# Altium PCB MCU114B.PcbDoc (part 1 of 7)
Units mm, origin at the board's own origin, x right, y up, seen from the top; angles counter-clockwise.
Board outline 105.51 x 58.76 mm, 8 copper layers (Top Layer, GND 2, Signal Layer 3, Power 4, Power 5, Signal Layer 6, GND 7, Bottom), stack 1.554 mm thick; 444 components, 418 nets, 1811 pads, 981 vias.
Unrouted connection lines stored in the file: 3.
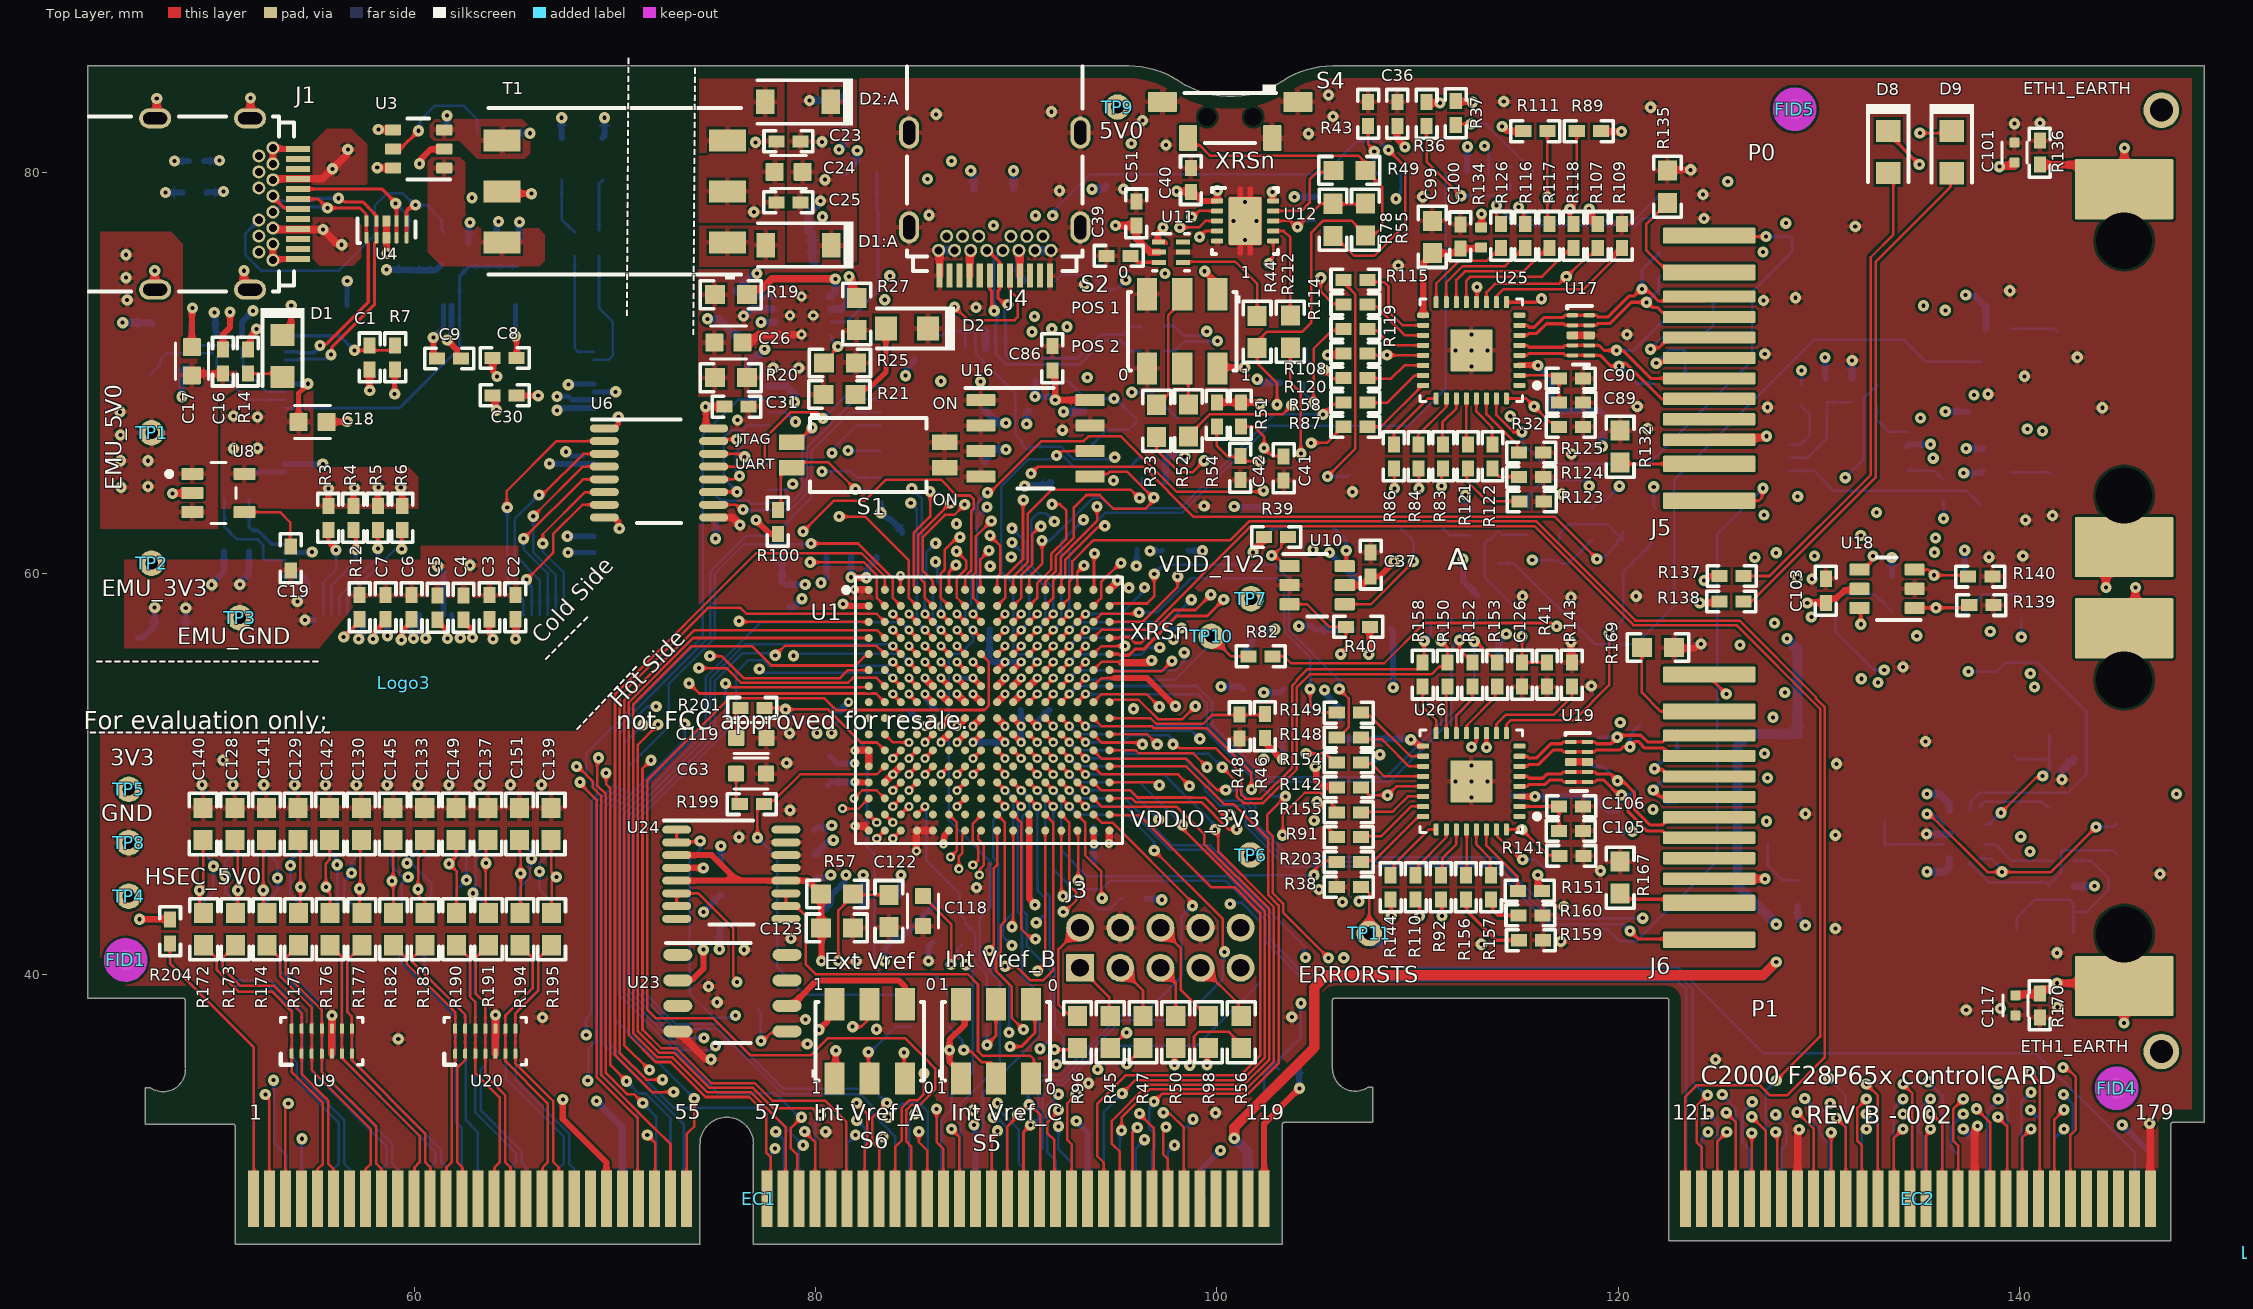
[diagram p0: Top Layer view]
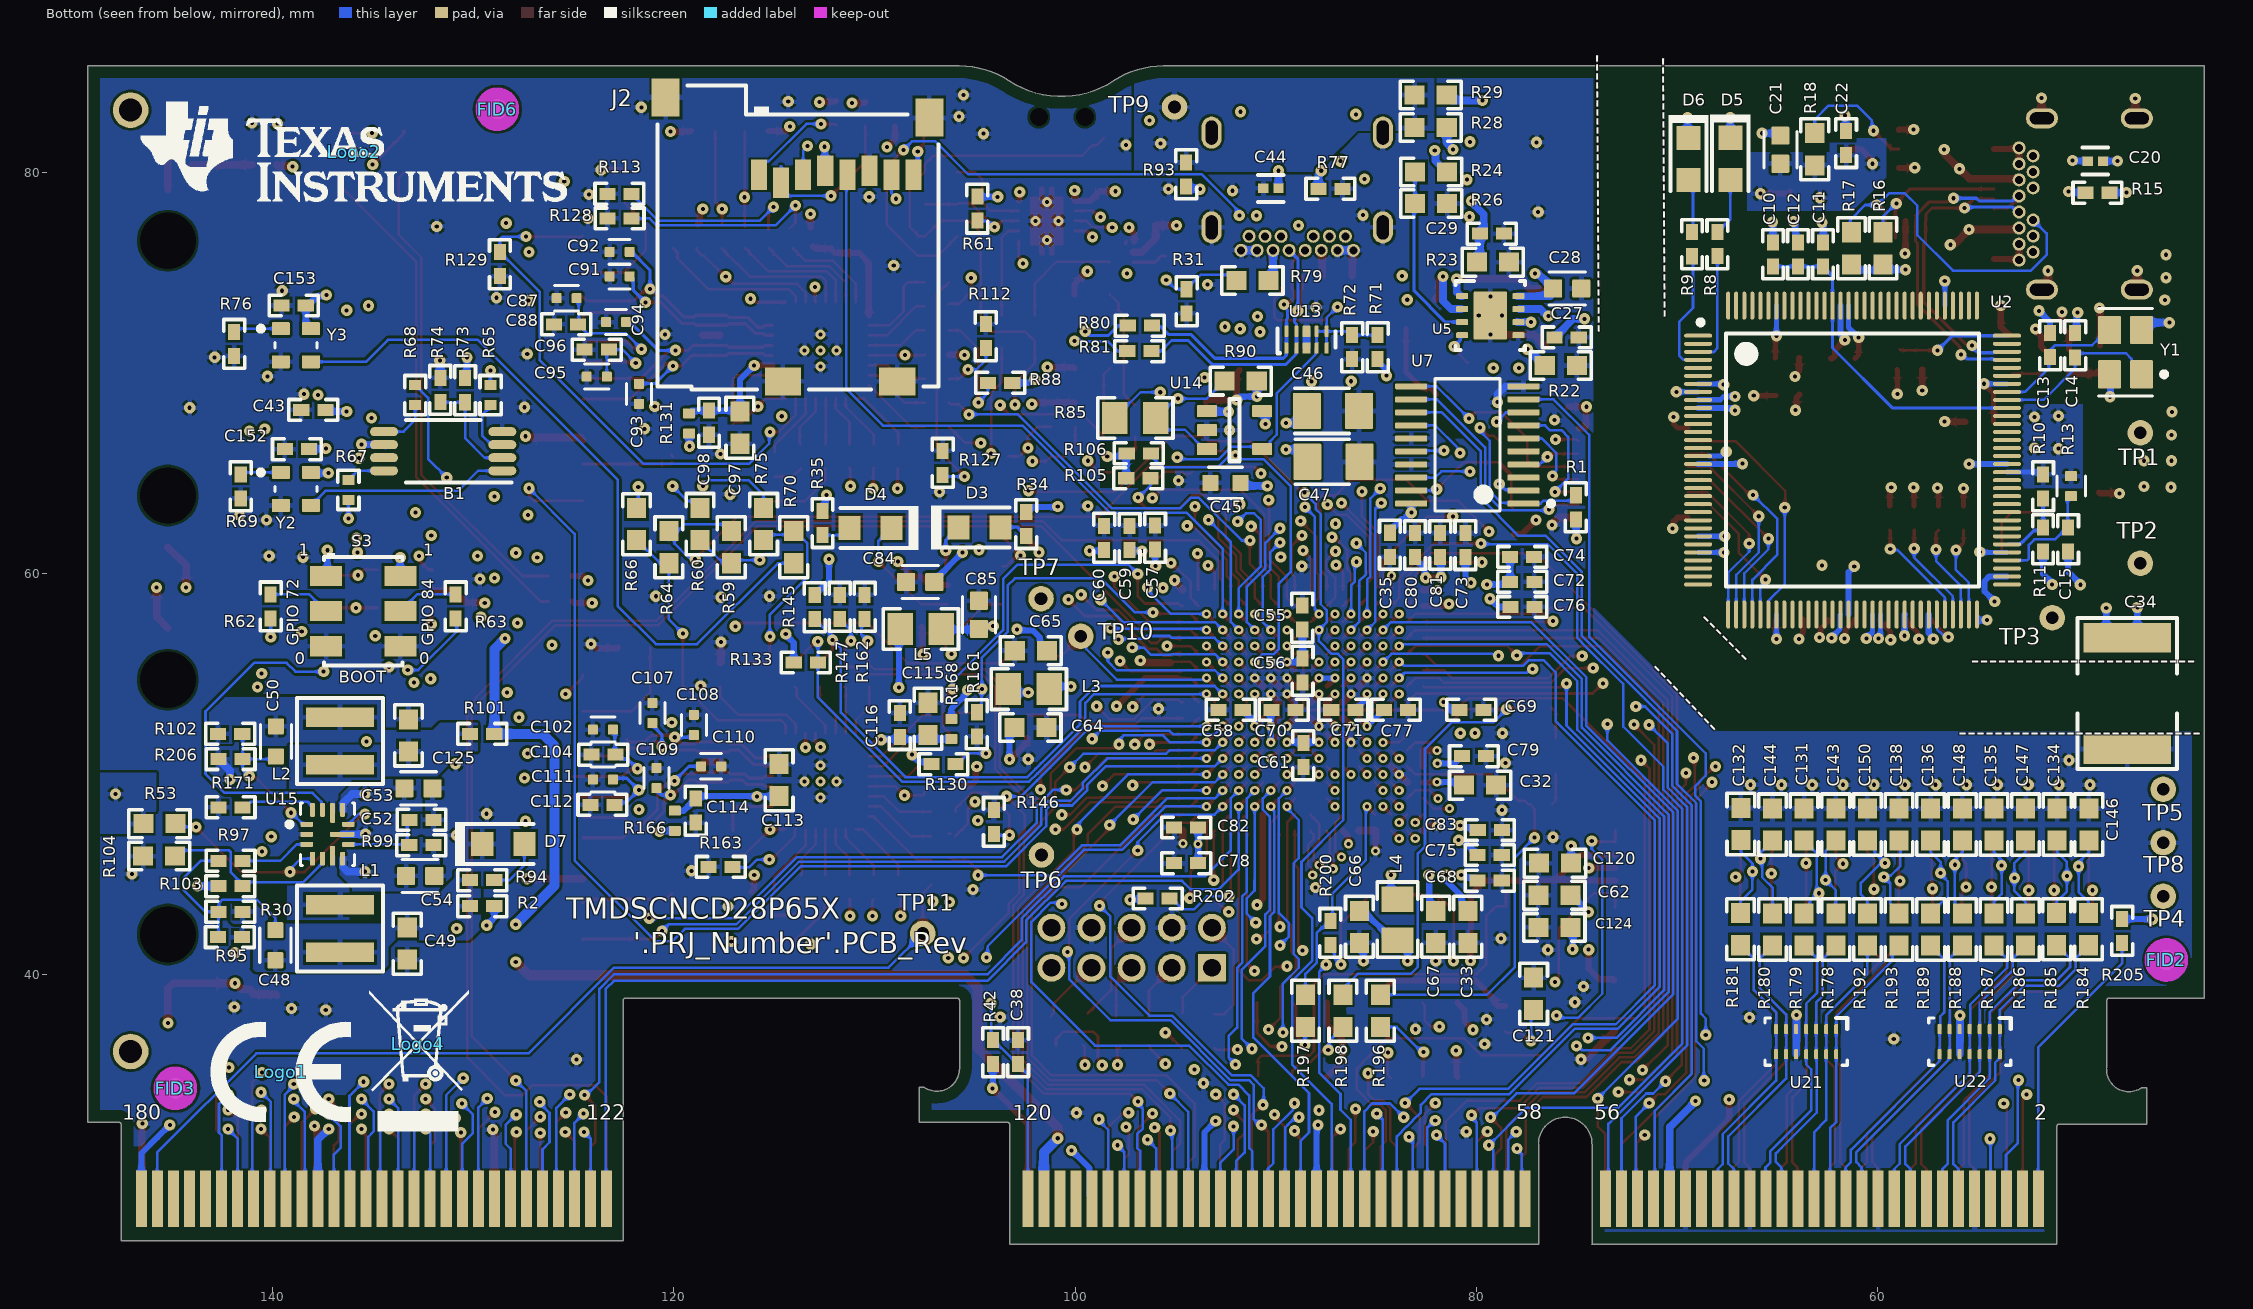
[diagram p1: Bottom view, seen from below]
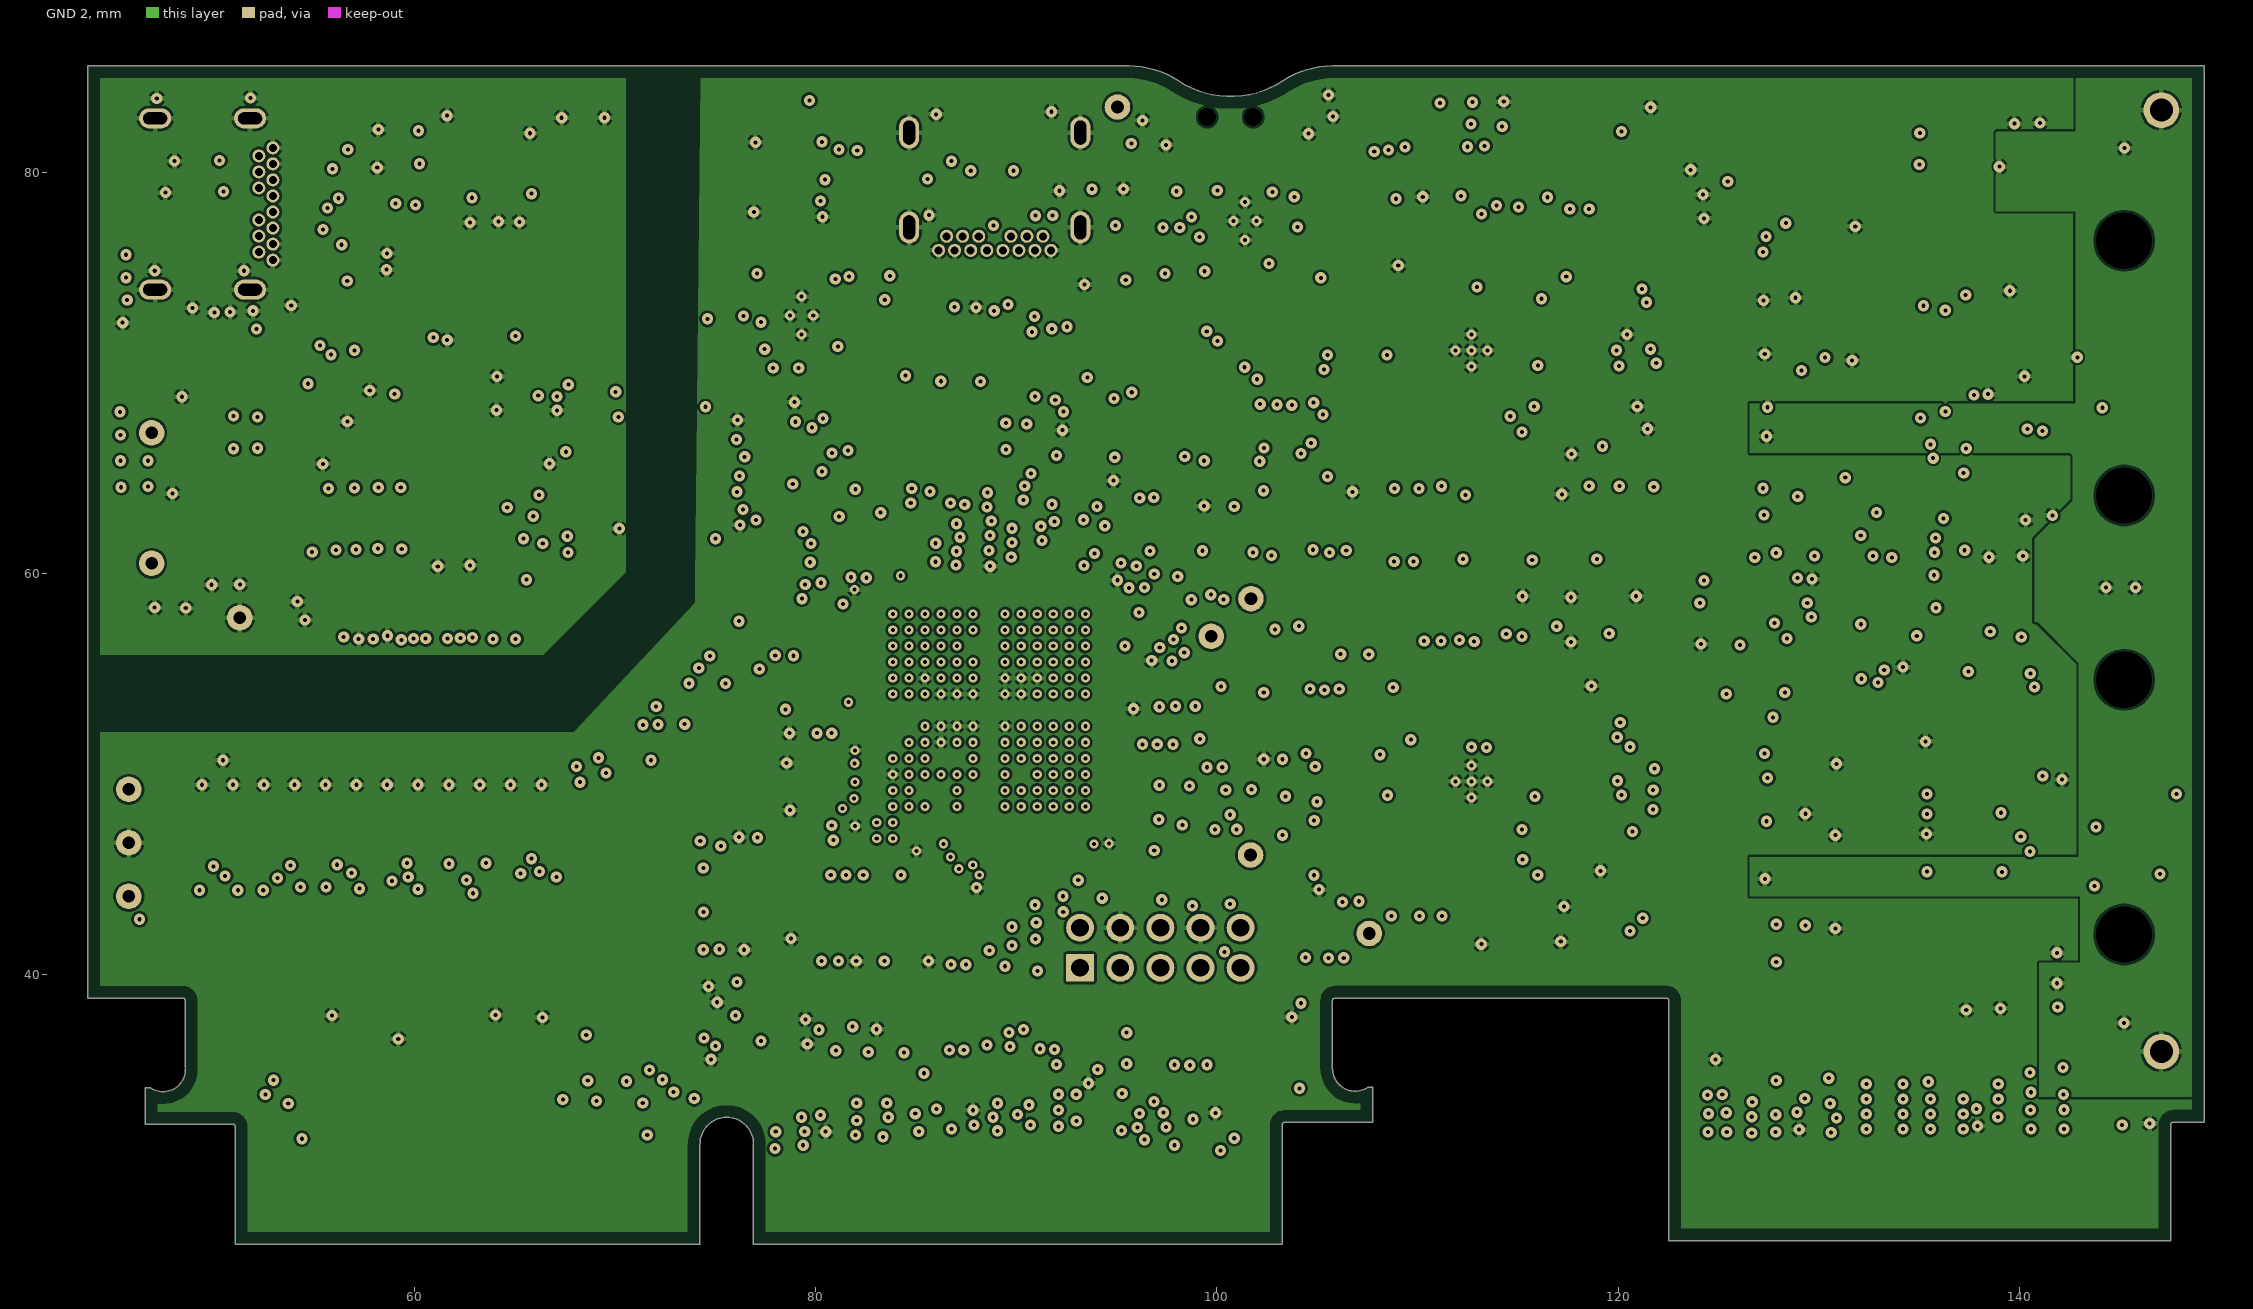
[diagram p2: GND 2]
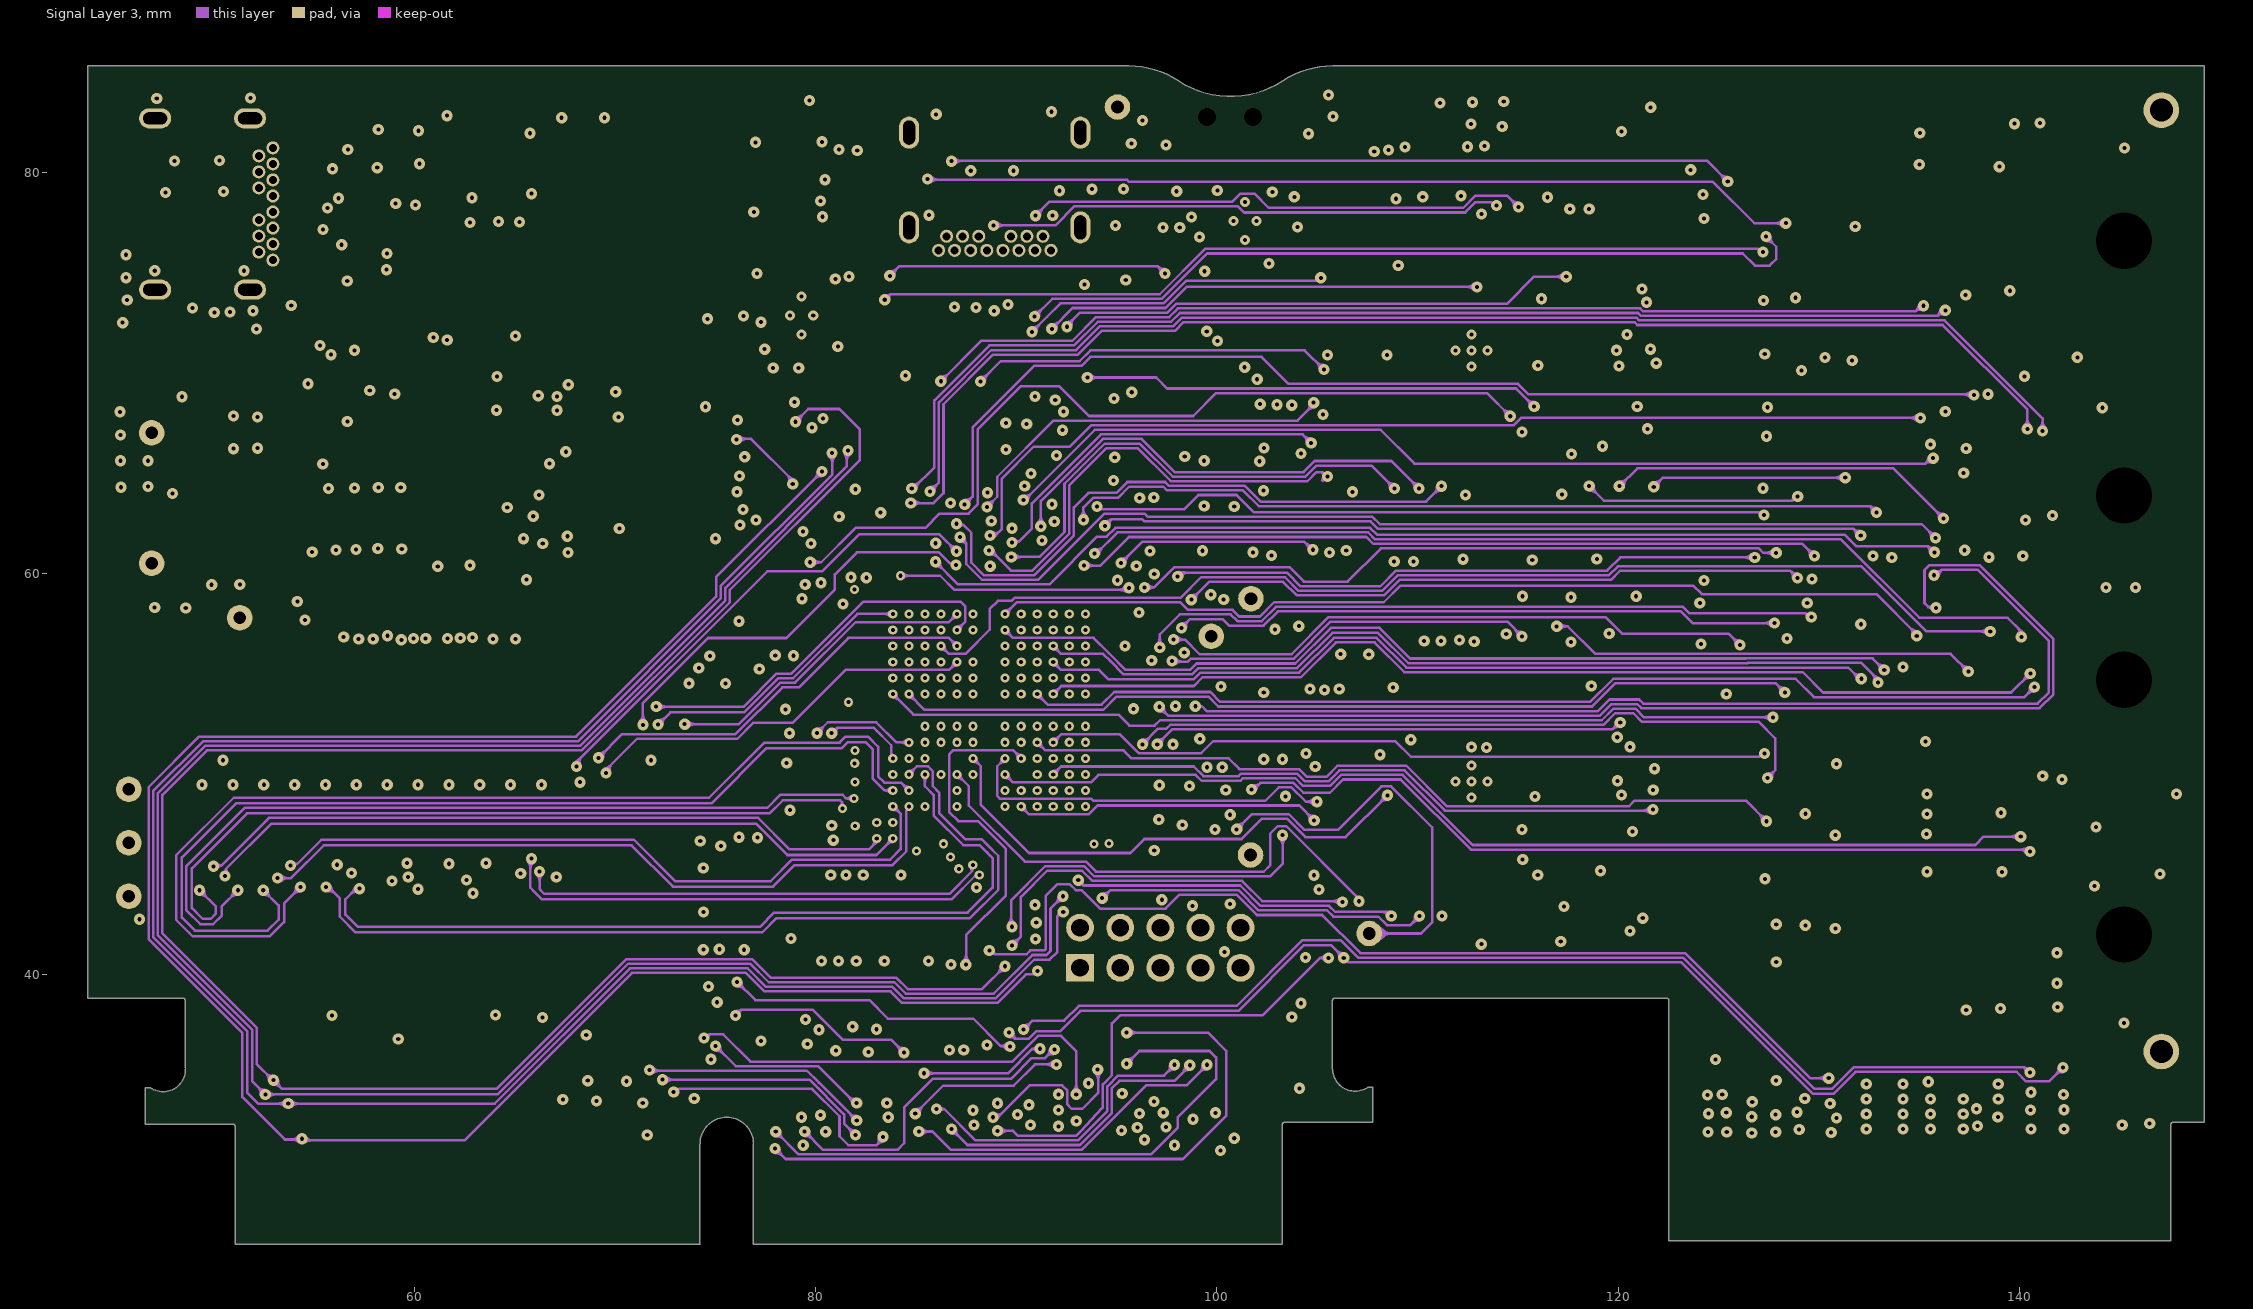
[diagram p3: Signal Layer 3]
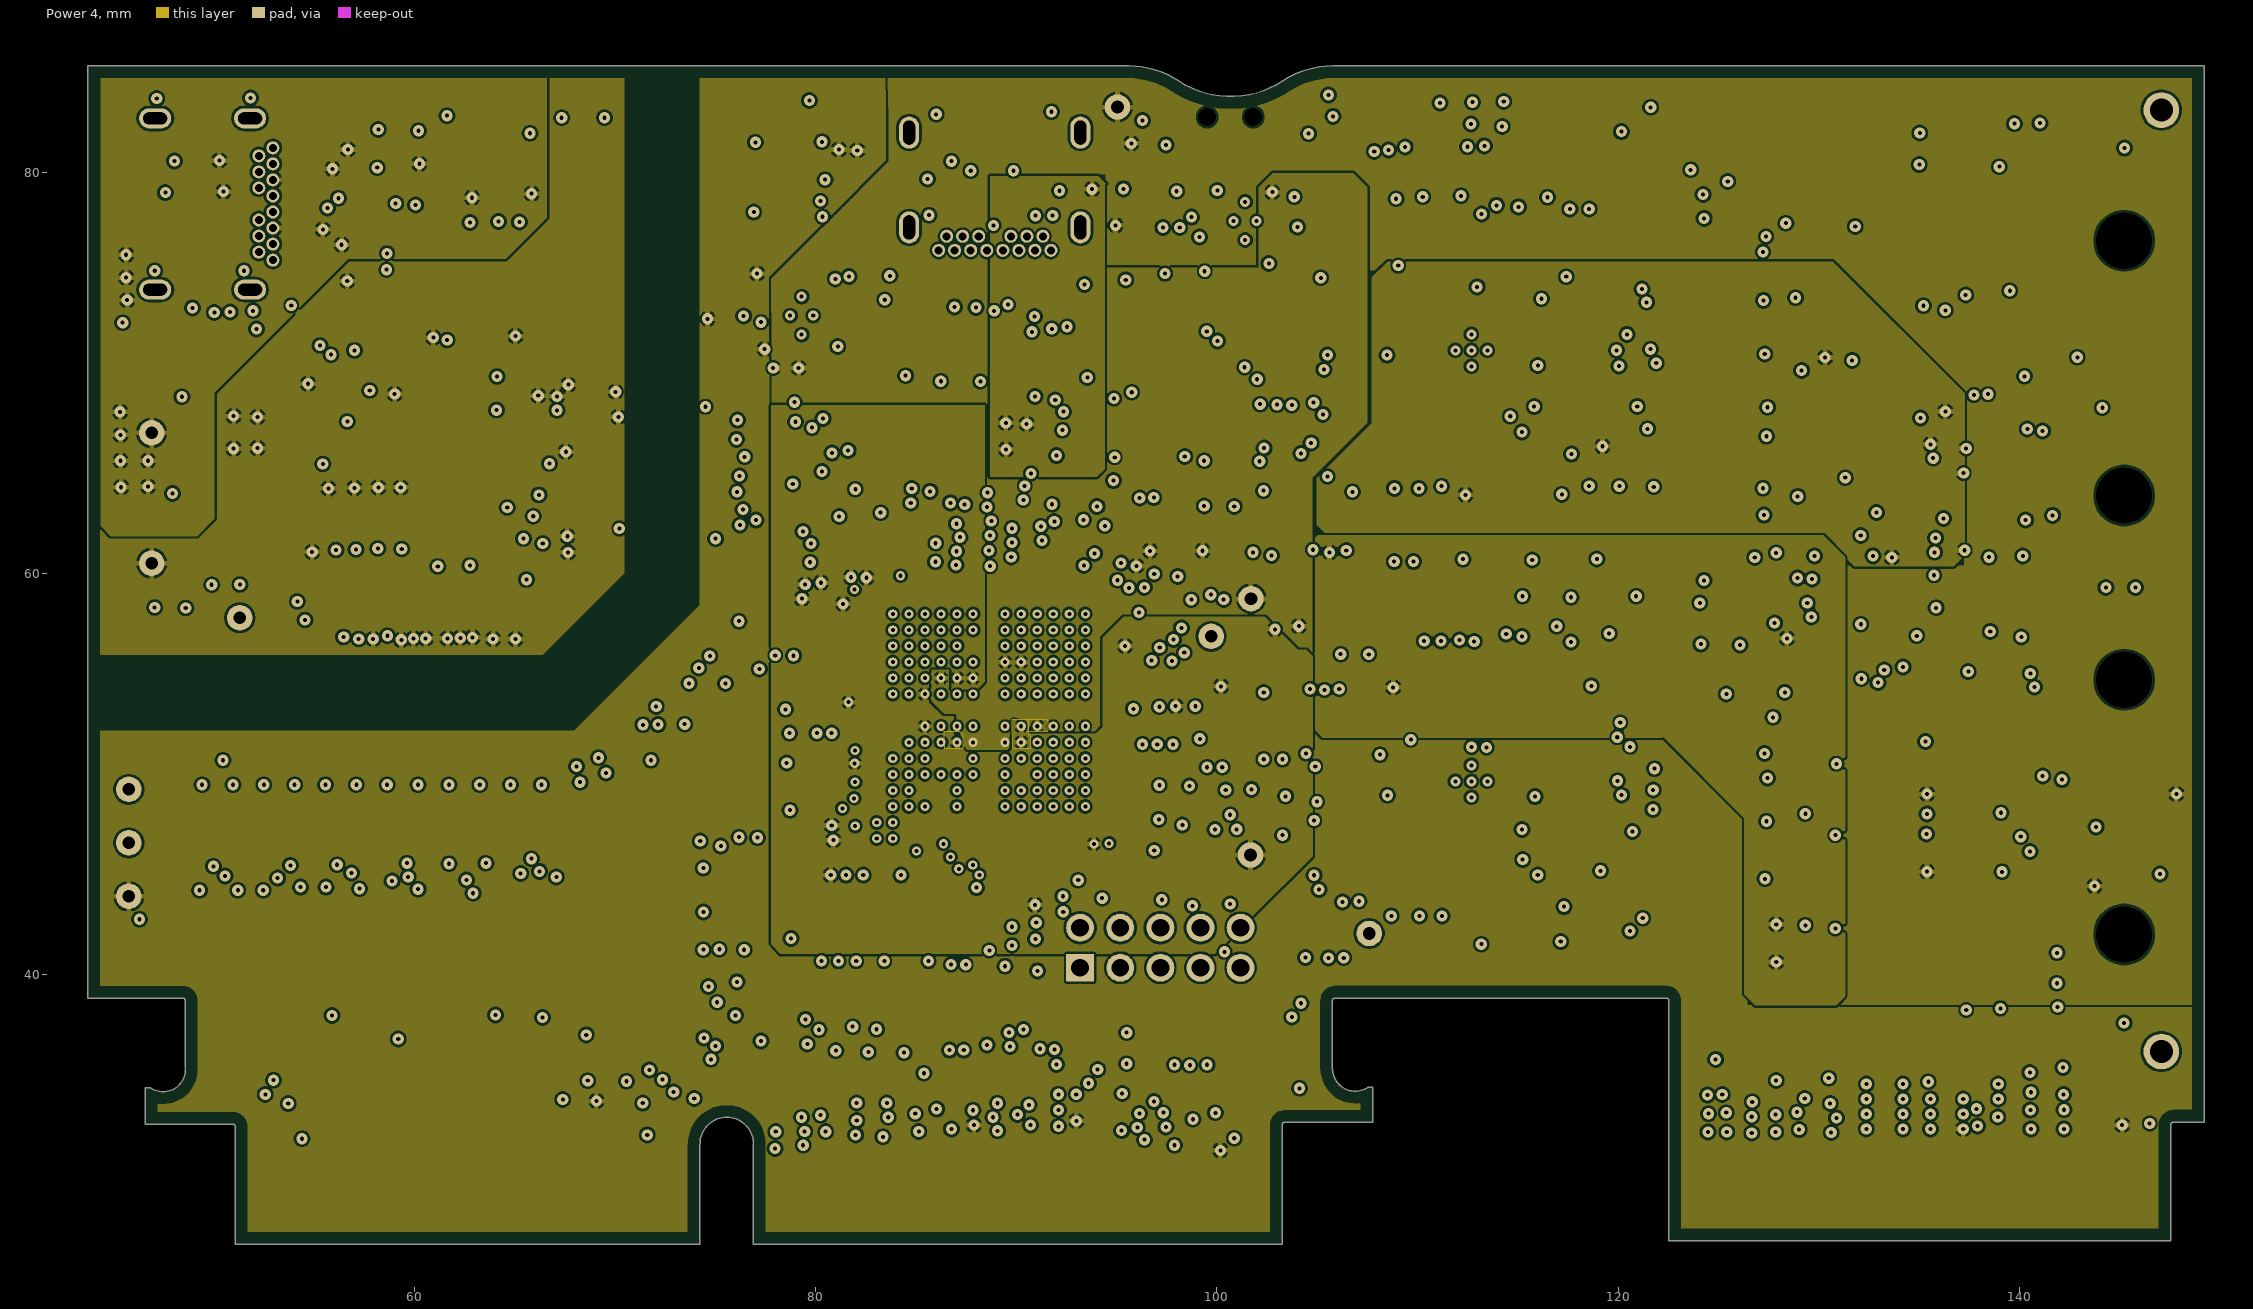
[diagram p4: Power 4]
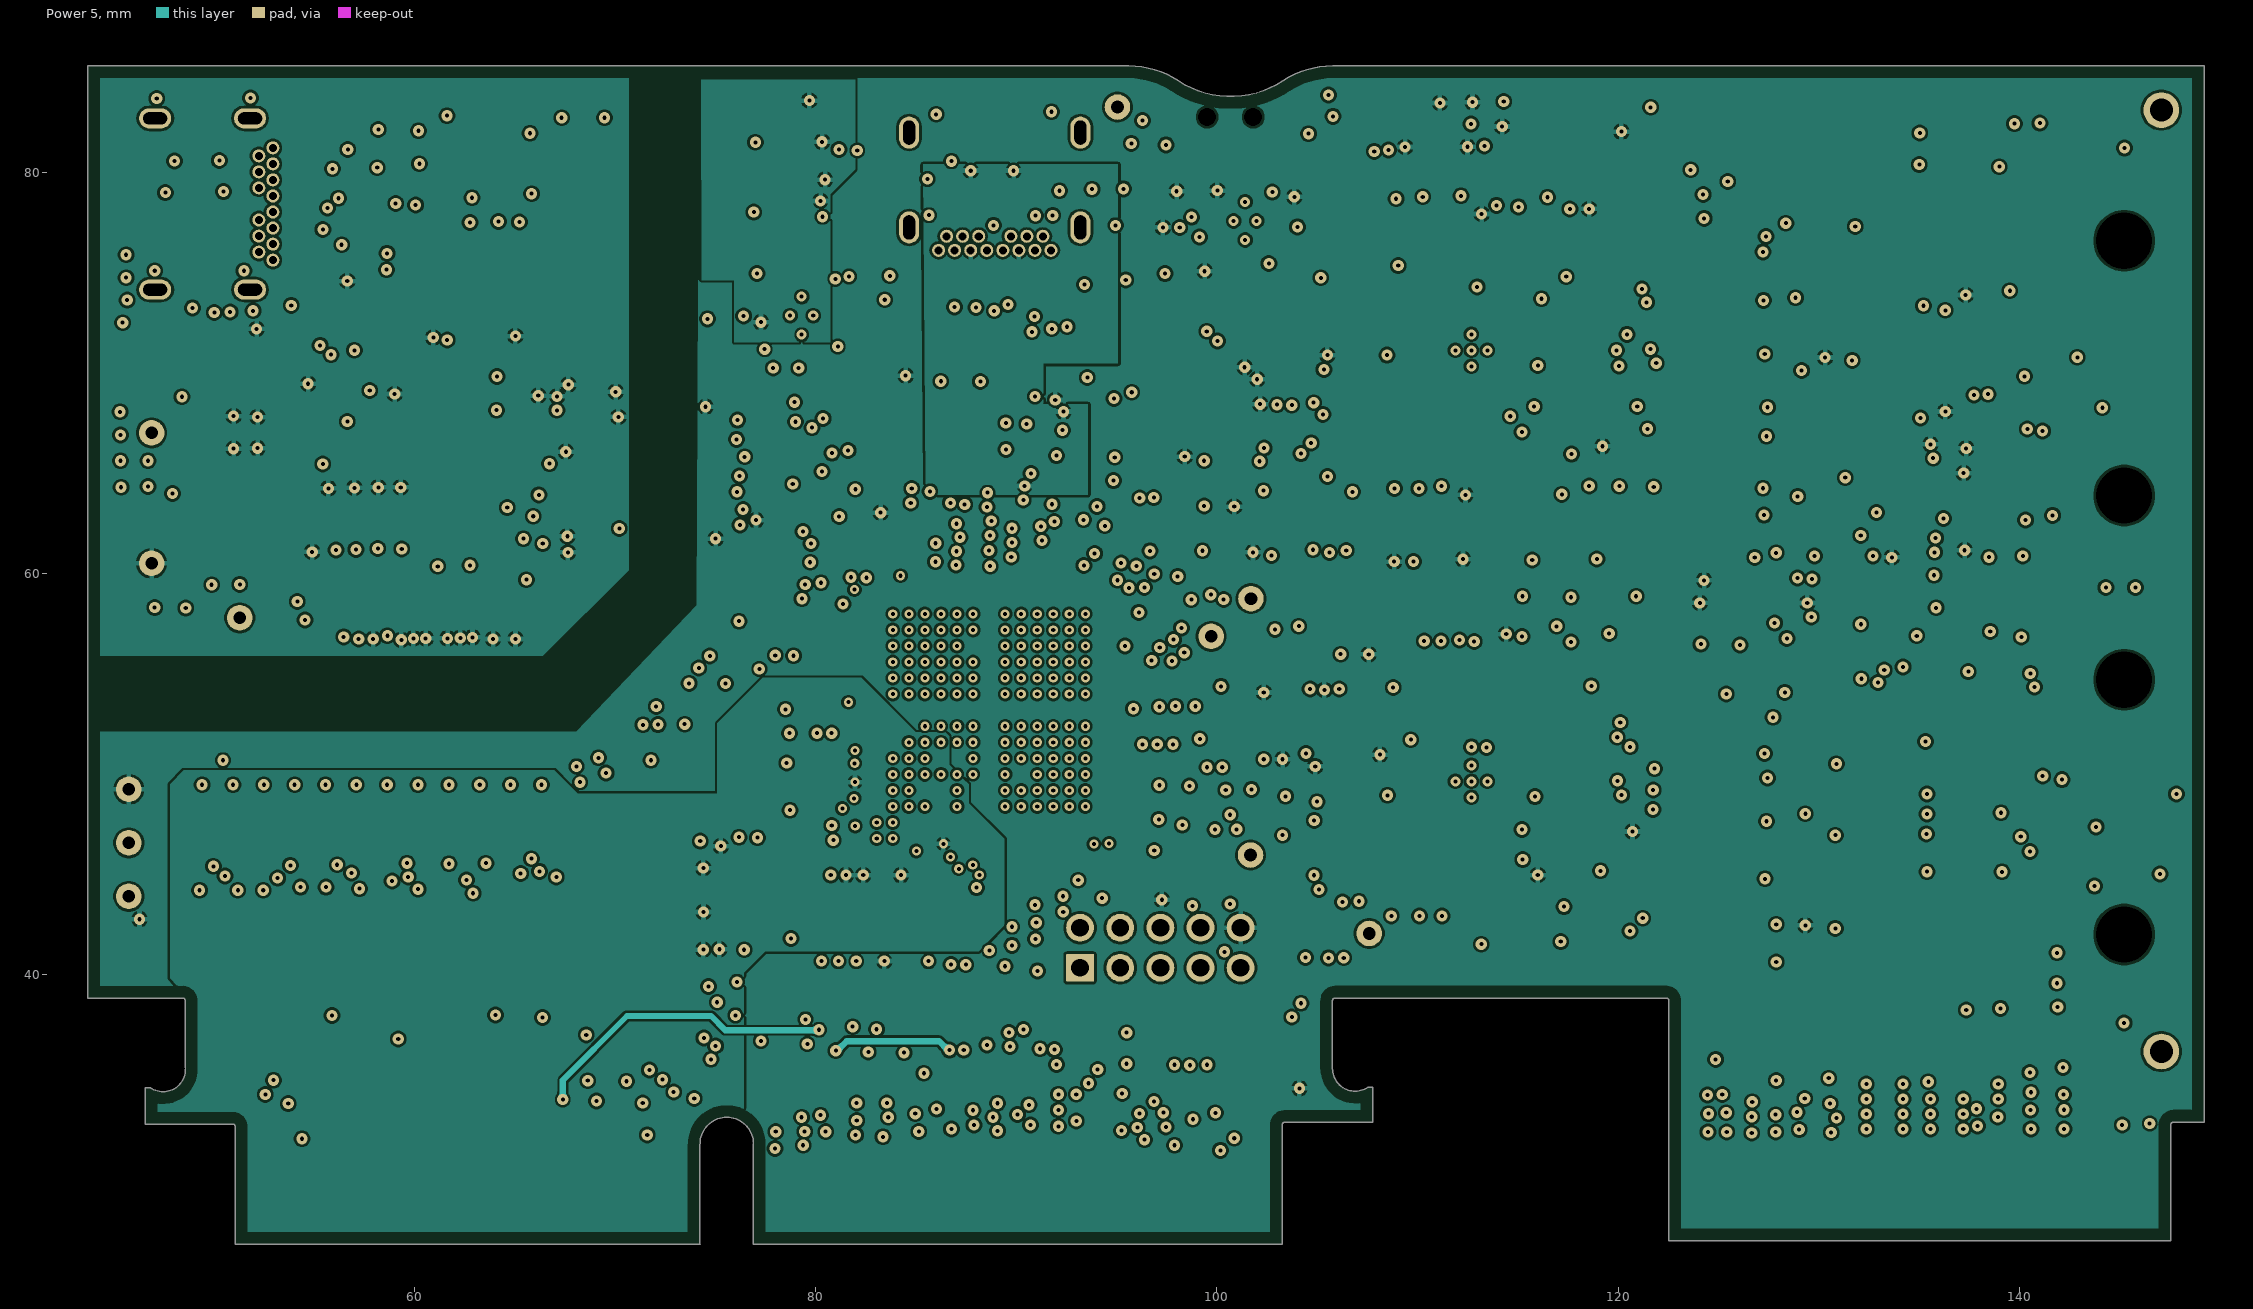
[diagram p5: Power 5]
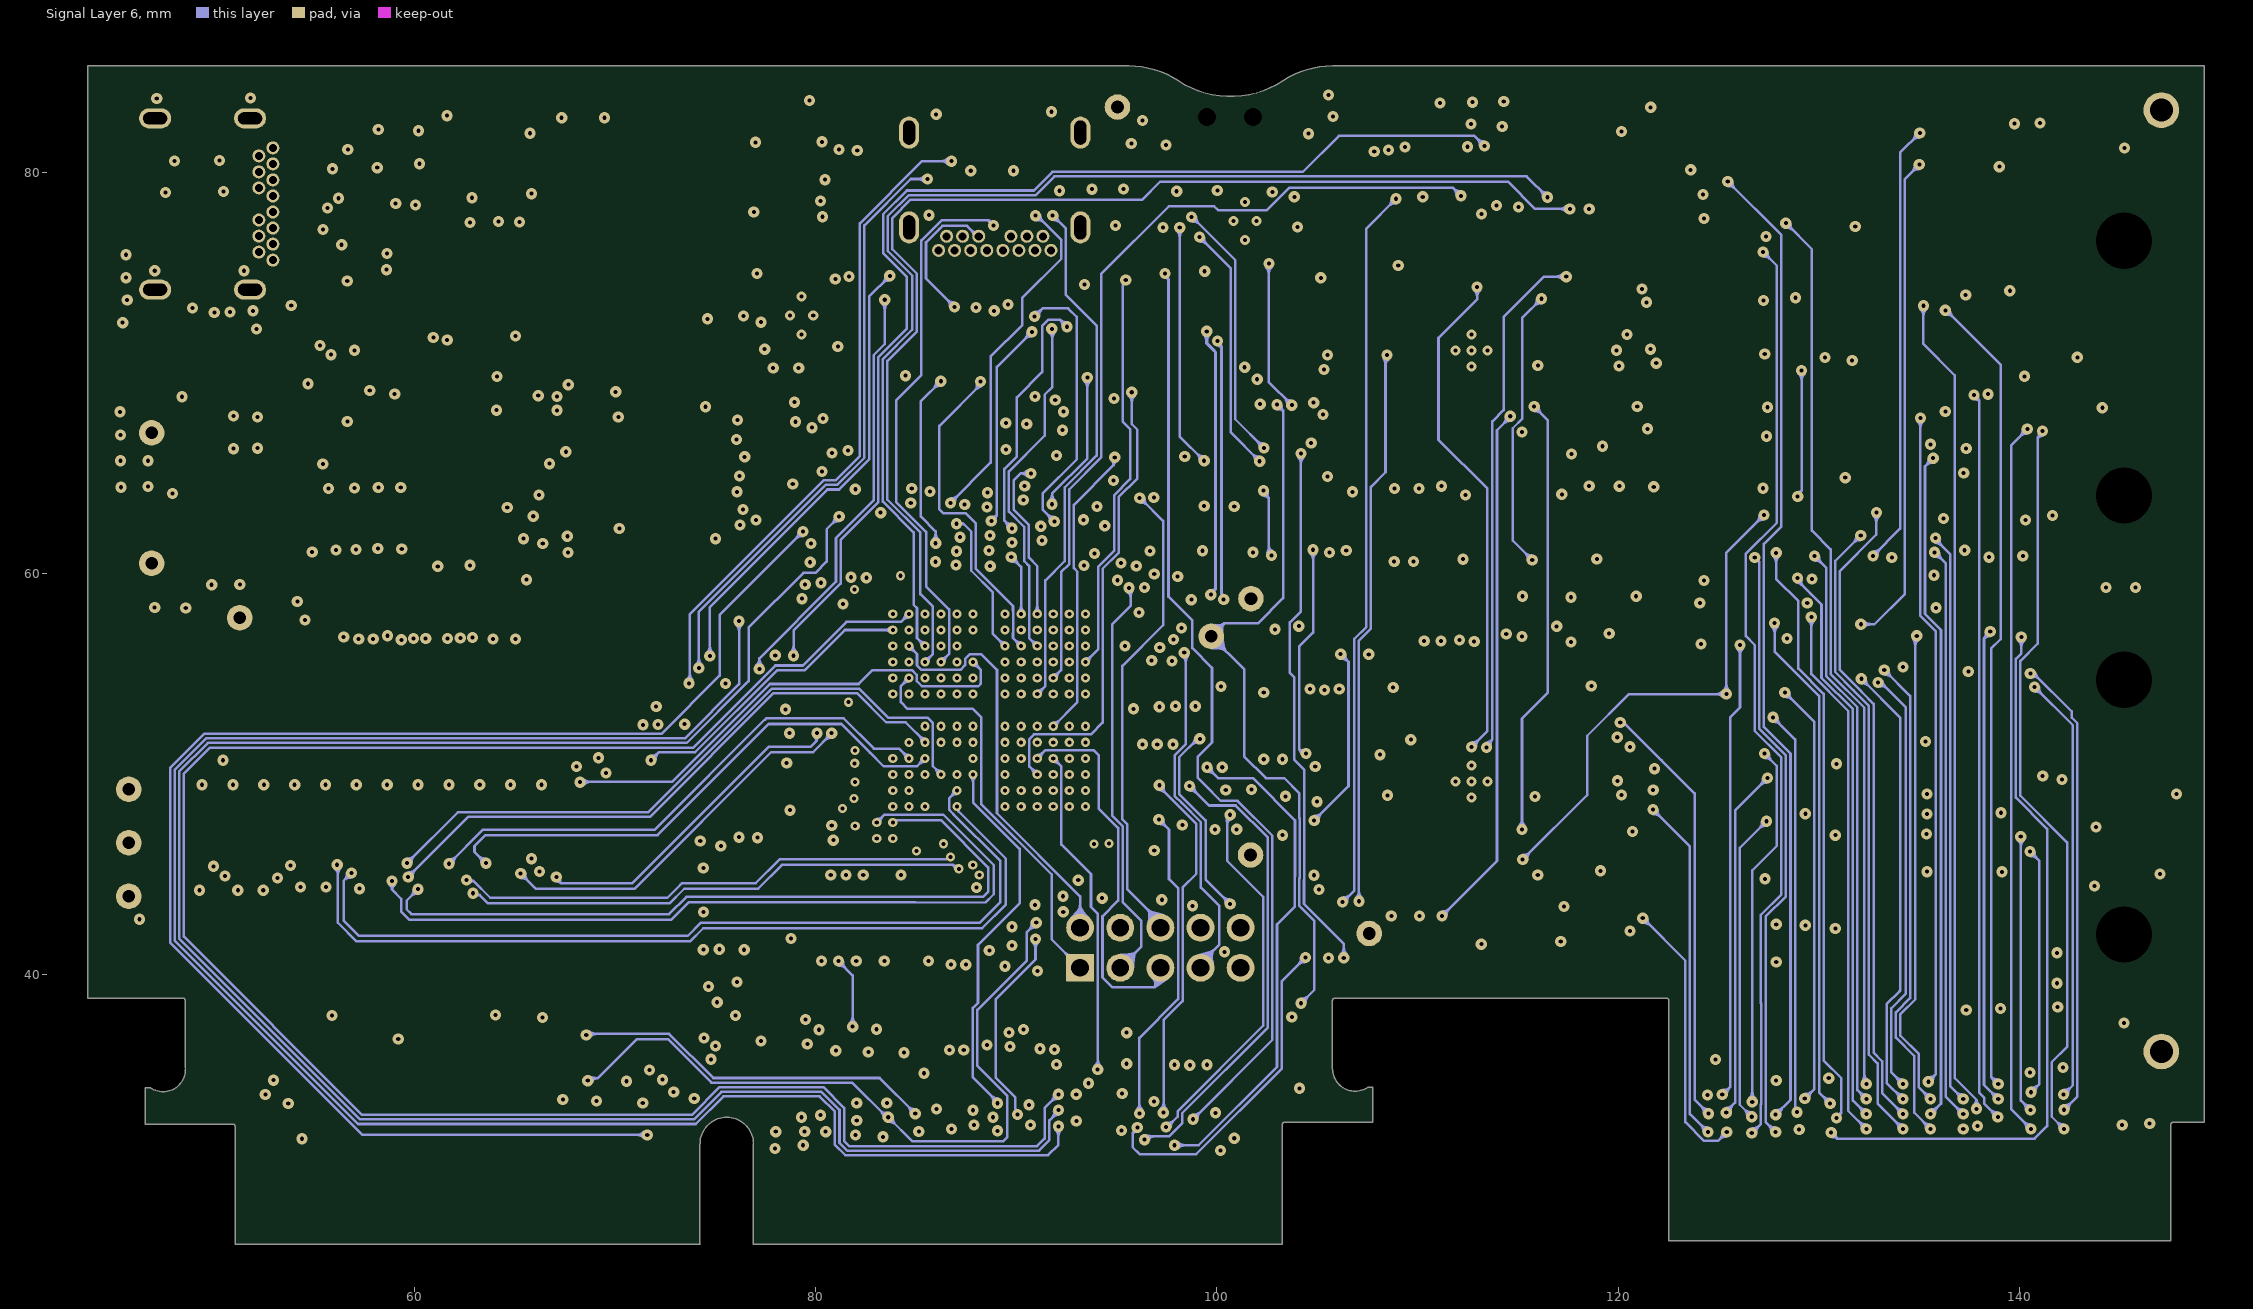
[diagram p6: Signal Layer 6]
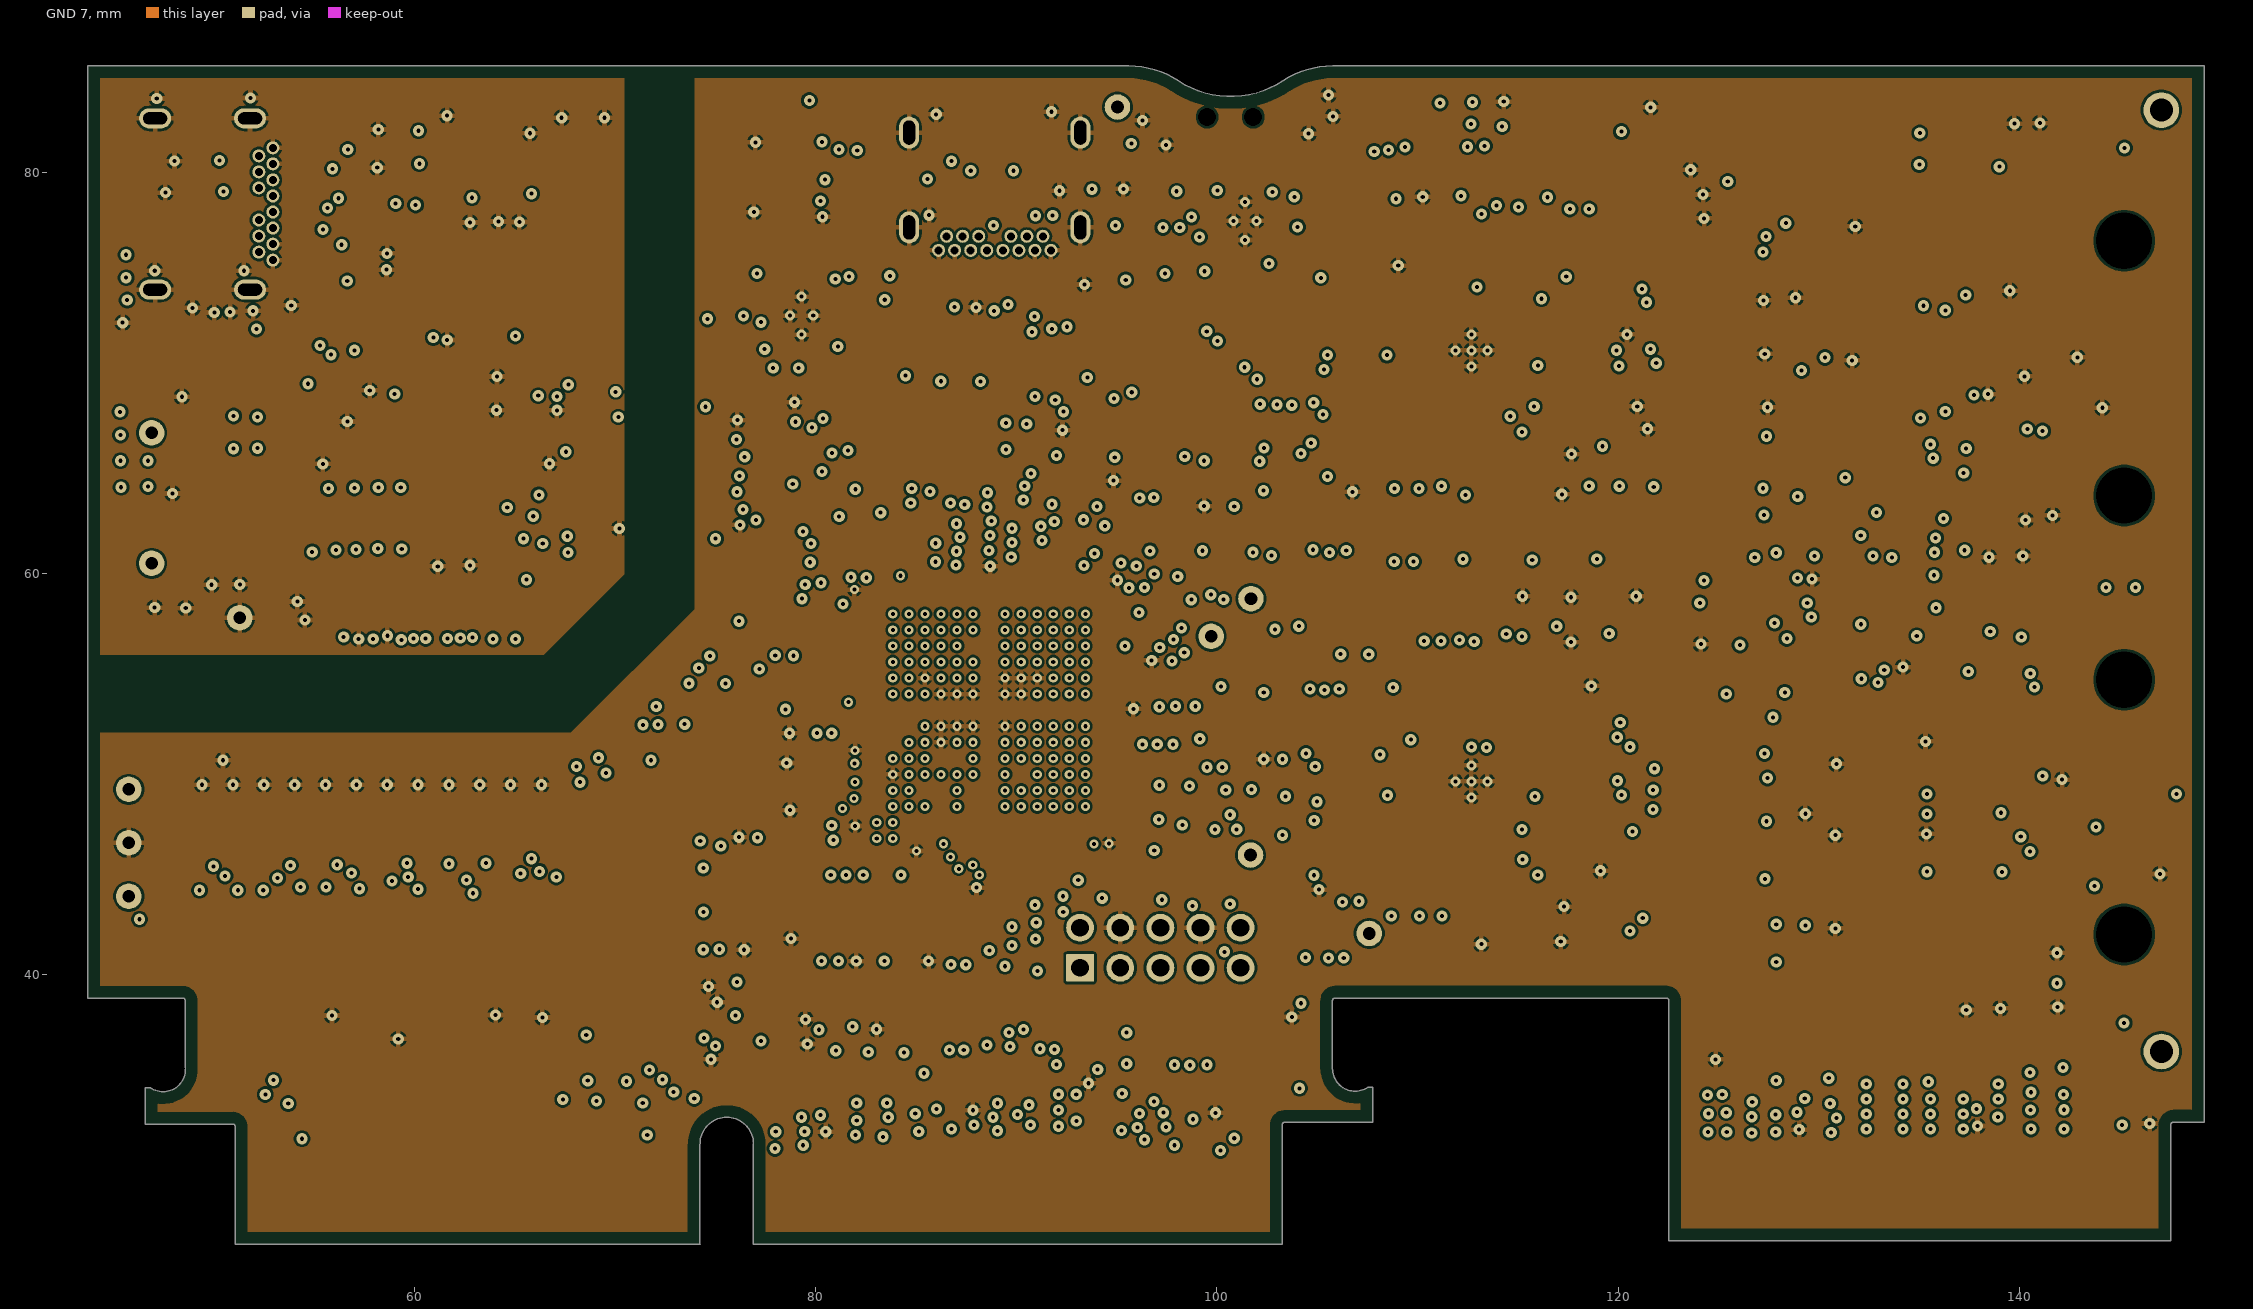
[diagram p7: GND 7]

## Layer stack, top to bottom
Top Solder: solder mask 0.0127, Solder Resist, Dk 3.6
Top Layer: signal copper 0.0356
Dielectric 1: prepreg 0.127, FR-4, Dk 3.7
GND 2: signal copper 0.0356
Dielectric 2: core 0.254, FR-4, Dk 3.7
Signal Layer 3: signal copper 0.0356
Dielectric 3: prepreg 0.127, FR-4, Dk 3.7
Power 4: signal copper 0.0356
Dielectric 4: core 0.254, FR-4, Dk 3.7
Power 5: signal copper 0.0356
Dielectric 5: prepreg 0.127, FR-4, Dk 3.7
Signal Layer 6: signal copper 0.0356
Dielectric 6: core 0.254, FR-4, Dk 3.7
GND 7: signal copper 0.0356
Dielectric 7: prepreg 0.127, FR-4, Dk 3.7
Bottom: signal copper 0.0356
Bottom Solder: solder mask 0.0127, Solder Resist, Dk 3.6

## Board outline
46.579,32.563 50.927,32.563 cw(c50.927,32.436) 51.054,32.436 51.054,26.568 51.075,26.57 74.23,26.57 74.225,26.606 74.225,31.546 74.228,31.572 cw(c75.561,31.561) 76.895,31.572 76.895,31.571 76.895,26.563 76.896,26.561 103.255,26.563 103.253,26.584 103.253,32.434 103.261,32.476 cw(c103.381,32.519) 103.381,32.646 107.767,32.646 107.767,34.398 107.529,34.398 cw(c106.891,35.316) 105.775,35.254 105.76,35.313 105.76,38.716 cw(c105.888,38.716) 105.888,38.844 122.405,38.844 cw(c122.405,38.716) 122.533,38.716 122.533,26.753 147.558,26.753 147.558,32.521 cw(c147.686,32.521) 147.686,32.649 149.22,32.649 149.22,85.318 105.842,85.318 105.766,85.318 ccw(c105.766,80.831) 103.296,84.577 cw(c100.686,88.536) 98.075,84.577 ccw(c95.606,80.831) 95.606,85.318 95.602,85.318 43.709,85.318 43.709,38.844 48.433,38.844 cw(c48.433,38.716) 48.56,38.716 48.56,35.394 48.574,35.29 cw(c47.456,35.29) 46.817,34.373 46.579,34.373

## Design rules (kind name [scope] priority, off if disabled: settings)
AcuteAngle [All] p1: minimum=4.50000000000000E+0001 checktracksonly=TRUE
AssemblyTestPointUsage [All] p1: valid=2
BoardOutlineClearance "Edge exception" [OnCopper and Not InComponentClass('Logo') and not InComponentClass('FiducialMark') and not InRegion(1000,500,4000,800) and not InPoly and ((Name = 'EC2') or (Name = 'EC1'))] p1: gap=0 ignorepadtopadclearanceinfootprint=FALSE
BoardOutlineClearance [All] p2: gap=0.61 ignorepadtopadclearanceinfootprint=FALSE except(0: Text-OutlineEdge; 0.381: Arc-OutlineEdge Track-OutlineEdge SMDPad-OutlineEdge Fill-OutlineEdge)
BoardOutlineClearance BoardOutlineClearance_MountingHoles [OnCopper and InComponentClass('Mounting Holes')] p3: gap=1.016 ignorepadtopadclearanceinfootprint=FALSE
BoardOutlineClearance BoardOutlineClearance_Poly [OnCopper and IsPoly] p4: gap=0.635 ignorepadtopadclearanceinfootprint=FALSE
Clearance "Clearance_RJ45 pad" [InComponent('J5') OR InComponent('J6')] p1: gap=0.127 ignorepadtopadclearanceinfootprint=TRUE except(0: SMDPad-THPad)
Clearance Clearance_Keepouts [((IsTrack Or IsArc) And Not InPoly) And IsFree and IsKeepOut vs ((IsTrack Or IsArc) And Not InPoly) And IsFree and IsKeepOut] p2: gap=0.127 ignorepadtopadclearanceinfootprint=FALSE
Clearance Clearance_Poly [InPolygon] p3: gap=0.127 ignorepadtopadclearanceinfootprint=FALSE
Clearance Clearance_FiducialMark [IsKeepOut and InComponentClass('FiducialMark') vs IsPad and InComponentClass('FiducialMark')] p4: gap=0 ignorepadtopadclearanceinfootprint=FALSE
Clearance [All] p5: gap=0.127 ignorepadtopadclearanceinfootprint=FALSE except(0.102: Arc-Arc Arc-Track Arc-Via Track-Track Track-Via)
ComponentClearance ComponentClearance_TI_LOGO [InComponentClass('Logo')] p1: gap=0 collisioncheckmode=3 verticalgap=0 showdistances=FALSE
ComponentClearance ComponentClearance_MountingHoles_FiducialMarks [InComponentClass('Mounting Holes') vs InComponentClass('FiducialMark')] p2: gap=0.254 collisioncheckmode=3 verticalgap=0.254 showdistances=FALSE
ComponentClearance ComponentClearance_Shunt [InComponentClass('Header') vs InComponentClass('Shunt')] p3: gap=0 collisioncheckmode=3 verticalgap=0 showdistances=FALSE
ComponentClearance ComponentClearance_Logo [InComponentClass('Logo')] p4: gap=0.254 collisioncheckmode=3 verticalgap=0.254 showdistances=FALSE
ComponentClearance ComponentClearance_ScrewToNut [(HasFootprint('NY PMS 440 0025 PH')) vs (HasFootprint('Keystone_1902C'))] p5: gap=0.127 collisioncheckmode=3 verticalgap=0.254 showdistances=FALSE
ComponentClearance ComponentClearance_MountingHoles [InComponentClass('Mounting Holes')] p6: gap=6.35 collisioncheckmode=3 verticalgap=2540 showdistances=FALSE
ComponentClearance ComponentClearance_SmallPassives [HasFootprint('0201*') or HasFootprint('0402*') or HasFootprint('0508') or HasFootprint('0603*') or HasFootprint('0612') or HasFootprint('0805*') or HasFootprint('0815*') or HasFootprint('0830*') or HasFootprint('1206*') or HasFootprint('1210*') or HasFootprint('1808*') or HasFootprint('1812*') or HasFootprint('1825*') or HasFootprint('2010*') or HasFootprint('2220*') or HasFootprint('2225*') or HasFootprint('2512*') or HasFootprint('2728*') or HasFootprint('3518*') vs HasFootprint('0201*') or HasFootprint('0402*') or HasFootprint('0508') or HasFootprint('0603*') or HasFootprint('0612') or HasFootprint('0805*') or HasFootprint('0815*') or HasFootprint('0830*') or HasFootprint('1206*') or HasFootprint('1210*') or HasFootprint('1808*') or HasFootprint('1812*') or HasFootprint('1825*') or HasFootprint('2010*') or HasFootprint('2220*') or HasFootprint('2225*') or HasFootprint('2512*') or HasFootprint('2728*') or HasFootprint('3518*')] p7: gap=0.38 collisioncheckmode=3 verticalgap=0.254 showdistances=FALSE
ComponentClearance ComponentClearance_THtoSMT [IsThruComponent vs IsSMTComponent] p8: gap=0.762 collisioncheckmode=3 verticalgap=0.762 showdistances=FALSE
ComponentClearance "ComponentClearance_TP to TP" [(INComponent('TP1:A') or InComponent('TP2:A') or InComponent('TP3:A')or InComponent('TP7') or InComponent('TP2') or InComponent('TP3') or InComponent('TP10')) vs (INComponent('TP1:A') or InComponent('TP2:A') or InComponent('TP3:A')or InComponent('TP7') or InComponent('TP2') or InComponent('TP3') or InComponent('TP10'))] p9: gap=0.508 collisioncheckmode=3 verticalgap=0.508 showdistances=FALSE
ComponentClearance ComponentClearance_THtoTH [IsThruComponent vs IsThruComponent] p10: gap=0.762 collisioncheckmode=3 verticalgap=0.762 showdistances=FALSE
ComponentClearance [All] p11: gap=0.254 collisioncheckmode=3 verticalgap=0.254 showdistances=FALSE
DiffPairsRouting [All] p1: maxlimit=0.254 minlimit=0.152 mostfreqgap=0.152 toplayer_minwidth=0.124 toplayer_maxwidth=0.157 toplayer_prefwidth=0.124 midlayer1_minwidth=0.124 midlayer1_maxwidth=0.157 midlayer1_prefwidth=0.124 midlayer2_minwidth=0.124 midlayer2_maxwidth=0.381 midlayer2_prefwidth=0.124 midlayer3_minwidth=0.124 midlayer3_maxwidth=0.381 midlayer3_prefwidth=0.124 midlayer4_minwidth=0.124 midlayer4_maxwidth=0.157 midlayer4_prefwidth=0.124 midlayer5_minwidth=0.124 midlayer5_maxwidth=0.381 midlayer5_prefwidth=0.124 midlayer6_minwidth=0.124 midlayer6_maxwidth=0.381 midlayer6_prefwidth=0.124 bottomlayer_minwidth=0.124 bottomlayer_maxwidth=0.157 bottomlayer_prefwidth=0.124 maxuncoupledlength=12.7
DiffPairsRouting DiffPairsRouting_90 [InDifferentialPairClass('All Differential Pairs')] p2: maxlimit=0.152 minlimit=0.127 mostfreqgap=0.152 toplayer_minwidth=0.152 toplayer_maxwidth=0.155 toplayer_prefwidth=0.155 midlayer1_mingap=0.152 midlayer1_minwidth=0.152 midlayer1_maxwidth=0.155 midlayer1_prefwidth=0.155 midlayer2_mingap=0.152 midlayer2_minwidth=0.152 midlayer2_maxwidth=0.155 midlayer2_prefwidth=0.155 midlayer3_mingap=0.152 midlayer3_minwidth=0.152 midlayer3_maxwidth=0.155 midlayer3_prefwidth=0.155 midlayer4_mingap=0.152 midlayer4_minwidth=0.152 midlayer4_maxwidth=0.155 midlayer4_prefwidth=0.155 midlayer5_mingap=0.152 midlayer5_minwidth=0.152 midlayer5_maxwidth=0.155 midlayer5_prefwidth=0.155 midlayer6_mingap=0.152 midlayer6_minwidth=0.152 midlayer6_maxwidth=0.155 midlayer6_prefwidth=0.155 bottomlayer_minwidth=0.152 bottomlayer_maxwidth=0.155 bottomlayer_prefwidth=0.155 maxuncoupledlength=25.4
FabricationTestPointUsage TestPointUsage [All] p1: valid=2 allowmultiple=FALSE
FabricationTestpoint Testpoint [All] p1: side=3 testpointundercomponent=TRUE minsize=1.016 maxsize=2.54 preferedsize=1.524 minholesize=0 maxholesize=1.016 preferedholesize=0.813 testpointgrid=0.025 allowsidetop=TRUE allowsidebottom=TRUE usegrid=TRUE gridtolerance=0
FanoutControl Fanout_LCC [IsLCC] p1: bgadir=Out bgaviamode=Centered fanoutstyle=Auto fanoutdirection=Alternating viagrid=0.025 // Fanout_LCC (Default Rule)
FanoutControl Fanout_BGA [IsBGA] p2: bgadir=Out bgaviamode=Centered fanoutstyle=Auto fanoutdirection=Alternating viagrid=0.025 // Fanout_BGA (Default Rule)
FanoutControl Fanout_Default [All] p4: bgadir=Out bgaviamode=Centered fanoutstyle=Auto fanoutdirection=Alternating viagrid=0.025 // Fanout_Default (Default Rule)
FanoutControl Fanout_Small [(CompPinCount < 5)] p5: bgadir=Out bgaviamode=Centered fanoutstyle=Auto fanoutdirection=OutThenIn viagrid=0.025 // Fanout_Small (Default Rule)
HoleSize [All] p1: absolutevalues=TRUE maxlimit=6.375 minlimit=0.2 maxpercent=80.000 minpercent=20.000
MinimumAnnularRing MinimumAnnularRing_ThermalPadVias [IsVia and InAnyComponent] p1: minimumring=0.124
MinimumAnnularRing [All] p2: minimumring=0.124
MinimumSolderMaskSliver MinimumSolderMaskSliver_Logo [InComponentClass('Logo') vs InComponentClass('Logo')] p1: minsoldermaskwidth=0.018
MinimumSolderMaskSliver [All] p2: minsoldermaskwidth=0.1
PlaneClearance PlaneClearance_1 [All] p1: clearance=0.254
PlaneClearance PlaneClearance_via [IsVia] p2: clearance=0.254
PlaneConnect [All] p1: planeconnectstyle=Relief reliefexpansion=0.254 reliefentries=4 reliefconductorwidth=0.254 reliefairgap=0.254
PolygonConnect 'POWER_4_VDDIO_3V3_P226' [Name = 'POWER_4_VDD_1V2_P187'] p1: connectstyle=Direct reliefconductorwidth=0.254 reliefentries=4 polygonreliefangle="90 Angle" airgapwidth=0.254
PolygonConnect PolygonConnect_1 [All] p2: connectstyle=Relief reliefconductorwidth=0.254 reliefentries=4 polygonreliefangle="90 Angle" airgapwidth=0.127
PolygonConnect PolygonConnect_via [isvia] p3: connectstyle=Relief reliefconductorwidth=0.254 reliefentries=4 polygonreliefangle="90 Angle" airgapwidth=0.127
RoutingVias [All] p1: holewidth=0.203 width=0.559 viastyle="Through Hole" minholewidth=0.2 minwidth=0.457 maxholewidth=0.203 maxwidth=0.559
ShortCircuit ShortCircuit_RJ45pad [InComponent('J5') And IsThruPin Or InComponent('J6') And IsThruPin] p1: allowed=TRUE // to prevent short ckt between deisngator ALIGN1 and ETH1_EARTH PAD
ShortCircuit [All] p2: allowed=FALSE
SilkToBoardRegionClearance [Not ((IsComment or IsDesignator) And (Hide <> 'False')) and not InRegion(1000,500,4000,800)] p1:
SilkToSilkClearance SilkToSilkClearance_Pb-FreeLogo [(HasFootprint('Pb-Free_Overlay_Medium') OR HasFootprint('Pb-Free_Overlay_Small')) vs (HasFootprint('Pb-Free_Overlay_Medium') OR HasFootprint('Pb-Free_Overlay_Small'))] p1: silktosilkclearance=0
SilkToSilkClearance [All] p2: silktosilkclearance=0.076
SilkToSolderMaskClearance SilkToComponentPadClearance [(IsPad or IsFill or IsRegion) and InAnycomponent] p1: minsilkscreentomaskgap=0.076 clearancetoexposedcopper=TRUE
SilkToSolderMaskClearance "Silk to Solder Mask Opening" [All] p2: minsilkscreentomaskgap=0.076 clearancetoexposedcopper=FALSE
SolderMaskExpansion [All] p1: expansion=0.05 istentingtop=FALSE
UnRoutedNet [All] p1: checkbadconnections=TRUE
Width USB_Width [InNetClass('USB')] p1: maxlimit=0.159 minlimit=0.155 preferedwidth=0.159 checkconnectedcopper=TRUE
Width [All] p2: maxlimit=0.508 minlimit=0.127 preferedwidth=0.127 checkconnectedcopper=TRUE
12 further rules are at their usual default settings.

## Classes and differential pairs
component class MCU114B_EVM_Hardware: !PCB1 FID1 FID2 FID3 FID4 FID5 FID6 Logo1 Logo2 Logo3 Logo4 Logo5 ZZ1 ZZ2 ZZ3 ZZ4
component class Logo: Logo2 Logo5
component class FiducialMark: FID1 FID2 FID3 FID4 FID5 FID6
component class AssemblyNote: ZZ1 ZZ2 ZZ3 ZZ4
component class MCU114B_XDS110_USB_Power: C16 C17 C18 C19 C20 C21 C22 C23 C24 C25 C26 C27 C28 C29 D1 D1:A D2 D2:A J1 R14 R15 R16 R17 R18 R19 R20 R21 R22 R23 R24 R25 R26 R27 R28 R29 T1 TP1 TP2 TP3 U3 U4 U5 U8
component class MCU114B_XDS110_MCU: C1 C2 C3 C4 C5 C6 C7 C8 C9 C10 C11 C12 C13 C14 C15 D5 D6 R3 R4 R5 R6 R7 R8 R9 R10 R11 R12 R13 U2 Y1
component class MCU114B_USB: C44 C45 C46 C47 J4 R31 R71 R72 R77 R79 R80 R81 R85 R90 U13 U14
component class MCU114B_Support: B1 C36 C37 C38 C39 C40 C41 C42 C43 C51 C126 C152 C153 D3 D4 J2 J3 R33 R34 R35 R36 R37 R38 R39 R40 R41 R42 R43 R44 R45 R46 R47 R48 R49 R50 R51 R52 R54 R55 R56 R59 R60 R61 R62 R63 R64 R65 R66 R67 R68 R69 R70 R73 R74 R75 R76 R78 R96 R98 R202 R212 S2 S3 S4 TP10 TP11 U10 U11 U12 Y2 Y3
component class MCU114B_Power: C32 C33 C48 C49 C50 C52 C53 C54 C55 C56 C57 C58 C59 C60 C61 C64 C65 C66 C67 C68 C69 C70 C71 C72 C73 C74 C75 C76 C77 C78 C79 C80 C81 C82 C83 C84 C85 C125 D7 L1 L2 L3 L4 L5 R2 R30 R53 R82 R93 R94 R95 R97 R99 R101 R102 R103 R104 R171 R206 TP4 TP5 TP6 TP7 TP8 TP9 U15
component class MCU114B_GPIOs: EC1 EC2 R204 R205
component class MCU114B_EtherCAT: C86 C87 C88 C89 C90 C91 C92 C93 C94 C95 C96 C97 C98 C99 C100 C101 C102 C103 C104 C105 C106 C107 C108 C109 C110 C111 C112 C113 C114 C115 C116 C117 D8 D9 J5 J6 R32 R58 R83 R84 R86 R87 R88 R89 R91 R92 R105 R106 R107 R108 R109 R110 R111 R112 R113 R114 R115 R116 R117 R118 R119 R120 R121 R122 R123 R124 R125 R126 R127 R128 R129 R130 R131 R132 R133 R134 R135 R136 R137 R138 R139 R140 R141 R142 R143 R144 R145 R146 R147 R148 R149 R150 R151 R152 R153 R154 R155 R156 R157 R158 R159 R160 R161 R162 R163 R166 R167 R168 R169 R170 R203 U16 U17 U18 U19 U25 U26
component class MCU114B_Emulator_Interface: C30 C31 C34 C35 R1 R100 S1 U6 U7
component class MCU114B_ADC: C62 C63 C118 C119 C120 C121 C122 C123 C124 C128 C129 C130 C131 C132 C133 C134 C135 C136 C137 C138 C139 C140 C141 C142 C143 C144 C145 C146 C147 C148 C149 C150 C151 R57 R172 R173 R174 R175 R176 R177 R178 R179 R180 R181 R182 R183 R184 R185 R186 R187 R188 R189 R190 R191 R192 R193 R194 R195 R196 R197 R198 R199 R200 R201 S5 S6 U1 U9 U20 U21 U22 U23 U24
differential pair MCU_D: +MCU_D_P -MCU_D_N
differential pair MCU_C10C11: +MCU_C10C11_P -MCU_C10C11_N
differential pair MCU_C2C3: +MCU_C2C3_P -MCU_C2C3_N
differential pair MCU_B4B5: +MCU_B4B5_P -MCU_B4B5_N
differential pair MCU_B2B3: +MCU_B2B3_P -MCU_B2B3_N
differential pair MCU_B0B1: +MCU_B0B1_P -MCU_B0B1_N
differential pair MCU_A14B14C14A15B15C15: +MCU_A14B14C14A15B15C15_P -MCU_A14B14C14A15B15C15_N
differential pair MCU_A10A11: +MCU_A10A11_P -MCU_A10A11_N
differential pair MCU_A8A9: +MCU_A8A9_P -MCU_A8A9_N
differential pair MCU_A4A5: +MCU_A4A5_P -MCU_A4A5_N
differential pair MCU_A2A3: +MCU_A2A3_P -MCU_A2A3_N
differential pair MCU_A0A1: +MCU_A0A1_P -MCU_A0A1_N
differential pair HSEC_ADC_C10C11: +HSEC_ADC_C10C11_P -HSEC_ADC_C10C11_N
differential pair HSEC_ADC_C2C3: +HSEC_ADC_C2C3_P -HSEC_ADC_C2C3_N
differential pair HSEC_ADC_B4B5: +HSEC_ADC_B4B5_P -HSEC_ADC_B4B5_N
differential pair HSEC_ADC_B2B3: +HSEC_ADC_B2B3_P -HSEC_ADC_B2B3_N
differential pair HSEC_ADC_B0B1: +HSEC_ADC_B0B1_P -HSEC_ADC_B0B1_N
differential pair HSEC_ADC_A14B14C14A15B15C15: +HSEC_ADC_A14B14C14A15B15C15_P -HSEC_ADC_A14B14C14A15B15C15_N
differential pair HSEC_ADC_A10A11: +HSEC_ADC_A10A11_P -HSEC_ADC_A10A11_N
differential pair HSEC_ADC_A8A9: +HSEC_ADC_A8A9_P -HSEC_ADC_A8A9_N
differential pair HSEC_ADC_A4A5: +HSEC_ADC_A4A5_P -HSEC_ADC_A4A5_N
differential pair HSEC_ADC_A2A3: +HSEC_ADC_A2A3_P -HSEC_ADC_A2A3_N
differential pair HSEC_ADC_A0A1: +HSEC_ADC_A0A1_P -HSEC_ADC_A0A1_N
differential pair XDS_D: +XDS_D_P -XDS_D_N
differential pair USB_D: +USB_D_P -USB_D_N
differential pair PHY1_TD: +PHY1_TD_P -PHY1_TD_N
differential pair PHY1_RD: +PHY1_RD_P -PHY1_RD_N
differential pair PHY0_TD: +PHY0_TD_P -PHY0_TD_N
differential pair PHY0_RD: +PHY0_RD_P -PHY0_RD_N

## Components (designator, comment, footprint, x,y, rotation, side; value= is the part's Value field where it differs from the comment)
B1 "LMK1C1104PW" PW0008A_N 131.507,66.108 r0 bottom
C1 "885012205031" 0402 57.756,70.782 r270 top value=0.01uF
C2 "885012205031" 0402 65.026,58.33 r90 top value=0.01uF
C3 "885012205031" 0402 63.731,58.33 r90 top value=0.01uF
C4 "885012205031" 0402 62.436,58.304 r90 top value=0.01uF
C5 "885012205037" 0402 61.14,58.304 r90 top value=0.1uF
C6 "885012205037" 0402 59.845,58.33 r90 top value=0.1uF
C7 "885012105012" 0402 58.549,58.33 r90 top value=1uF
C8 "885012105012" 0402 64.487,70.756 r180 top value=1uF
C9 "885012205031" 0402 61.719,70.731 r0 top value=0.01uF
C10 "885012105013" 0402 65.202,75.921 r90 bottom value=2.2uF
C11 "885012205037" 0402 62.713,75.921 r90 bottom value=0.1uF
C12 "885012105012" 0402 63.957,75.921 r90 bottom value=1uF
C13 "CL05C120JB5NNNC" 0402 51.384,71.399 r90 bottom value=12pF
C14 "CL05C120JB5NNNC" 0402 50.136,71.391 r90 bottom value=12pF
C15 "885012205037" 0402 50.491,61.711 r270 bottom value=0.1uF
C16 "885012205037" 0402 50.441,70.579 r90 top value=0.1uF
C17 "CC0603KRX5R7BB106" FP-CC0603KRX5R7BB106_0603-MFG 48.89,70.594 r270 top value=10µF
C18 "CC0603KRX5R7BB106" FP-CC0603KRX5R7BB106_0603-MFG 54.915,67.564 r180 top value=10µF
C19 "885012205031" 0402 53.823,60.766 r270 top value=0.01uF
C20 "CL05B332KB5NNNC" FP-CL388-IPC_C 49.128,80.57 r180 bottom
C21 "CC0603KRX5R7BB106" FP-CC0603KRX5R7BB106_0603-MFG 64.838,81.14 r90 bottom value=10µF
C22 "885012205037" 0402 61.56,81.472 r90 bottom value=0.1uF
C23 "885012205037" 0402 78.638,81.559 r180 top value=0.1uF
C24 "CC0603KRX5R7BB106" FP-CC0603KRX5R7BB106_0603-MFG 78.648,80.039 r0 top value=10µF
C25 "885012205037" 0402 78.634,78.518 r180 top value=0.1uF
C26 "CC0603KRX5R7BB106" FP-CC0603KRX5R7BB106_0603-MFG 75.641,71.526 r180 top value=10µF
C27 "885012205037" 0402 75.489,71.78 r180 bottom value=0.1uF
C28 "CC0603KRX5R7BB106" FP-CC0603KRX5R7BB106_0603-MFG 75.463,74.219 r0 bottom value=10µF
C29 "885012205037" 0402 79.219,76.954 r180 bottom value=0.1uF
C30 "885012205037" 0402 64.486,68.892 r180 top value=0.1uF
C31 "885012205037" 0402 76.048,68.326 r0 top value=0.1uF
C32 "885012106018" 0603 79.809,49.455 r180 bottom value=2.2uF
C33 "885012106018" 0603 80.42,42.392 r270 bottom value=2.2uF
C34 "C1812C100JHGACTU" 1812_180 47.546,54.028 r90 bottom value=10pF
C35 "885012205037" 0402 84.303,61.443 r270 bottom value=0.1uF
C36 "885012205037" 0402 108.996,82.923 r90 top value=0.1uF
C37 "885012205037" 0402 107.666,60.459 r90 top value=0.1uF
C38 "885012205037" 0402 102.845,36.144 r90 bottom value=0.1uF
C39 "885012205037" 0402 95.098,75.844 r180 top value=0.1uF
C40 "885012205037" 0402 98.704,79.629 r270 top value=0.1uF
C41 "885012205037" 0402 103.327,65.253 r90 top value=0.1uF
C42 "885012205037" 0402 101.168,65.278 r90 top value=0.1uF
C43 "885012205037" 0402 137.984,68.166 r0 bottom value=0.1uF
C44 "CL05B332KB5NNNC" FP-CL388-IPC_C 90.241,79.215 r0 bottom
C45 "885012106012" FP-885012106012_0603-MFG 92.504,64.533 r180 bottom value=4.7µF
C46 "293D104X9035A2TE3" 3216-18 87.144,68.115 r180 bottom value=0.1uF
C47 "TLJA686M010R1500" 3216-18 87.122,65.583 r180 bottom value=68uF
C48 "885012006032" FP-885012006032_0603-MFG 139.878,41.478 r270 bottom value=10pF
C49 "GRM188R61A226ME15D" 0603 133.299,41.554 r270 bottom value=22uF
C50 "885012006032" FP-885012006032_0603-MFG 139.852,51.638 r90 bottom value=10pF
C51 "885012205037" 0402 95.982,77.962 r90 top value=0.1uF
C52 "885012205037" 0402 132.588,47.727 r0 bottom value=0.1uF
C53 "CC0603KRX5R7BB106" FP-CC0603KRX5R7BB106_0603-MFG 132.74,49.301 r0 bottom value=10µF
C54 "CC0603KRX5R7BB106" FP-CC0603KRX5R7BB106_0603-MFG 132.653,44.933 r0 bottom value=10µF
C55 "885012205037" 0402 88.674,57.812 r90 bottom value=0.1uF
C56 "885012205037" 0402 88.66,55.169 r270 bottom value=0.1uF
C57 "885012205037" 0402 96.012,61.798 r90 bottom value=0.1uF
C58 "885012205037" 0402 92.241,53.214 r0 bottom value=0.1uF
C59 "885012205037" 0402 97.283,61.782 r90 bottom value=0.1uF
C60 "885012205037" 0402 98.554,61.787 r90 bottom value=0.1uF
C61 "885012205037" 0402 88.623,50.954 r270 bottom value=0.1uF
C62 "885012206046" 0603 76.098,43.967 r0 bottom value=0.1uF
C63 "885012106012" FP-885012106012_0603-MFG 76.774,50.035 r180 top value=4.7µF
C64 "885012106018" 0603 102.228,52.331 r180 bottom value=2.2uF
C65 "885012106018" 0603 102.21,56.159 r0 bottom value=2.2uF
C66 "885012106018" 0603 85.827,42.392 r270 bottom value=2.2uF
C67 "885012106018" 0603 82.017,42.392 r270 bottom value=2.2uF
C68 "885012205037" 0402 79.327,44.698 r180 bottom value=0.1uF
C69 "885012205037" 0402 80.241,53.214 r180 bottom value=0.1uF
C70 "885012205037" 0402 89.6,53.214 r180 bottom value=0.1uF
C71 "885012205037" 0402 86.629,53.214 r0 bottom value=0.1uF
C72 "885012205037" 0402 77.704,59.592 r180 bottom value=0.1uF
C73 "885012205037" 0402 80.536,61.429 r90 bottom value=0.1uF
C74 "885012205037" 0402 77.711,60.835 r180 bottom value=0.1uF
C75 "885012205037" 0402 79.327,45.976 r180 bottom value=0.1uF
C76 "885012205037" 0402 77.699,58.344 r180 bottom value=0.1uF
C77 "885012205037" 0402 84.002,53.214 r180 bottom value=0.1uF
C78 "885012205037" 0402 94.465,45.569 r0 bottom value=0.1uF
C79 "885012205037" 0402 80.112,50.902 r180 bottom value=0.1uF
C80 "885012205037" 0402 83.05,61.431 r90 bottom value=0.1uF
C81 "885012205037" 0402 81.796,61.431 r90 bottom value=0.1uF
C82 "885012205037" 0402 94.465,47.347 r0 bottom value=0.1uF
C83 "885012205037" 0402 79.324,47.219 r180 bottom value=0.1uF
C84 "CC0603KRX5R7BB106" FP-CC0603KRX5R7BB106_0603-MFG 107.721,59.588 r180 bottom value=10µF
C85 "CC0603KRX5R7BB106" FP-CC0603KRX5R7BB106_0603-MFG 104.796,57.953 r270 bottom value=10µF
C86 "885012205037" 0402 91.796,70.744 r270 top value=0.1uF
C87 "885012205086" FP-885012205086_0402-MFG 125.349,73.736 r180 bottom value=100nF
C88 "GRM155R61E105KE11D" 0402 125.374,72.437 r180 bottom value=1uF
C89 "C1005X5R1V225K050BC" 0402_065 117.664,68.526 r0 top value=2.2uF
C90 "885012205037" 0402 117.649,69.73 r0 top value=0.1uF
C91 "885012005053" FP-885012005053_0402-MFG 122.707,74.828 r0 bottom value=4.7pF
C92 "885012005053" FP-885012005053_0402-MFG 122.707,76.048 r0 bottom value=4.7pF
C93 "885012005053" FP-885012005053_0402-MFG 121.742,68.968 r270 bottom value=4.7pF
C94 "885012005053" FP-885012005053_0402-MFG 122.885,72.542 r0 bottom value=4.7pF
C95 "885012205086" FP-885012205086_0402-MFG 123.85,69.825 r180 bottom value=100nF
C96 "GRM155R61E105KE11D" 0402 123.85,71.171 r180 bottom value=1uF
C97 "GRM188R61A226ME15D" 0603 116.715,67.279 r270 bottom value=22uF
C98 "885012205037" 0402 118.254,67.528 r270 bottom value=0.1uF
C99 "GRM188R60J476ME15D" 0603 110.74,76.791 r90 top value=47uF
C100 "885012205037" 0402 112.137,76.816 r90 top value=0.1uF
C101 "885012205067" FP-885012205067_0402-MFG 139.761,80.996 r270 top value=10nF
C102 "885012205086" FP-885012205086_0402-MFG 123.547,52.229 r180 bottom value=100nF
C103 "885012205037" 0402 130.364,59.149 r90 top value=0.1uF
C104 "GRM155R61E105KE11D" 0402 123.52,50.978 r180 bottom value=1uF
C105 "C1005X5R1V225K050BC" 0402_065 117.649,47.175 r0 top value=2.2uF
C106 "885012205037" 0402 117.664,48.399 r0 top value=0.1uF
C107 "885012005053" FP-885012005053_0402-MFG 121.08,53.055 r90 bottom value=4.7pF
C108 "885012005053" FP-885012005053_0402-MFG 119.009,52.466 r90 bottom value=4.7pF
C109 "885012005053" FP-885012005053_0402-MFG 120.879,49.809 r90 bottom value=4.7pF
C110 "885012005053" FP-885012005053_0402-MFG 118.143,50.399 r180 bottom value=4.7pF
C111 "885012205086" FP-885012205086_0402-MFG 123.546,49.733 r180 bottom value=100nF
C112 "GRM155R61E105KE11D" 0402 123.567,48.476 r180 bottom value=1uF
C113 "GRM188R61A226ME15D" 0603 114.757,49.708 r90 bottom value=22uF
C114 "885012205037" 0402 118.914,48.189 r90 bottom value=0.1uF
C115 "GRM188R60J476ME15D" 0603 107.333,52.768 r90 bottom value=47uF
C116 "885012205037" 0402 108.737,52.454 r270 bottom value=0.1uF
C117 "885012205067" FP-885012205067_0402-MFG 139.813,38.481 r90 top value=10nF
C118 "885012106012" FP-885012106012_0603-MFG 85.344,43.18 r90 top value=4.7µF
C119 "885012106012" FP-885012106012_0603-MFG 76.785,51.805 r180 top value=4.7µF
C120 "885012106018" 0603 76.073,45.568 r0 bottom value=2.2uF
C121 "885012206052" 0603 77.137,39.057 r90 bottom value=1uF
C122 "885012206052" 0603 83.642,43.18 r270 top value=1uF
C123 "885012206052" 0603 81.051,42.342 r0 top value=1uF
C124 "885012206046" 0603 76.098,42.367 r0 bottom value=0.1uF
C125 "GRM188R61A226ME15D" 0603 133.234,51.935 r90 bottom value=22uF
C126 "885012205037" 0402 115.214,54.966 r90 top value=0.1uF
C128 "C0603C331J5GACTU" 0603 51.033,47.52 r90 top value=330pF
C129 "C0603C331J5GACTU" 0603 54.187,47.52 r90 top value=330pF
C130 "C0603C331J5GACTU" 0603 57.341,47.52 r90 top value=330pF
C131 "C0603C331J5GACTU" 0603 63.649,47.495 r90 bottom value=330pF
C132 "C0603C331J5GACTU" 0603 66.803,47.52 r90 bottom value=330pF
C133 "C0603C331J5GACTU" 0603 60.504,47.52 r90 top value=330pF
C134 "C0603C331J5GACTU" 0603 51.033,47.495 r90 bottom value=330pF
C135 "C0603C331J5GACTU" 0603 54.187,47.495 r90 bottom value=330pF
C136 "C0603C331J5GACTU" 0603 57.341,47.495 r90 bottom value=330pF
C137 "C0603C331J5GACTU" 0603 63.649,47.52 r90 top value=330pF
C138 "C0603C331J5GACTU" 0603 58.918,47.495 r90 bottom value=330pF
C139 "C0603C331J5GACTU" 0603 66.804,47.52 r90 top value=330pF
C140 "C0603C331J5GACTU" 0603 49.455,47.52 r90 top value=330pF
C141 "C0603C331J5GACTU" 0603 52.61,47.52 r90 top value=330pF
C142 "C0603C331J5GACTU" 0603 55.764,47.52 r90 top value=330pF
C143 "C0603C331J5GACTU" 0603 62.072,47.495 r90 bottom value=330pF
C144 "C0603C331J5GACTU" 0603 65.226,47.495 r90 bottom value=330pF
C145 "C0603C331J5GACTU" 0603 58.93,47.52 r90 top value=330pF
C146 "C0603C331J5GACTU" 0603 49.455,47.495 r90 bottom value=330pF
C147 "C0603C331J5GACTU" 0603 52.61,47.495 r90 bottom value=330pF
C148 "C0603C331J5GACTU" 0603 55.764,47.495 r90 bottom value=330pF
C149 "C0603C331J5GACTU" 0603 62.072,47.52 r90 top value=330pF
C150 "C0603C331J5GACTU" 0603 60.495,47.495 r90 bottom value=330pF
C151 "C0603C331J5GACTU" 0603 65.226,47.52 r90 top value=330pF
C152 "885012205037" 0402 138.797,66.21 r0 bottom value=0.1uF
C153 "885012205037" 0402 138.959,73.373 r0 bottom value=0.1uF
D1 "150080VS75000" WL-SMCW_Green_0805 53.413,70.858 r270 top value="Bright Green"
D1:A "1N5819HW-7-F" SOD-123 79.142,76.385 r180 top value=40V
D2 "150080SS75000" WL-SMCW_RED_0805 84.547,72.228 r180 top value=Red
D2:A "1N5819HW-7-F" SOD-123 79.117,83.522 r180 top value=40V
D3 "150080SS75000" WL-SMCW_RED_0805 104.772,62.298 r180 bottom value=Red
D4 "150080SS75000" WL-SMCW_RED_0805 110.206,62.288 r0 bottom value=Red
D5 "LTST-C170TBKT" LTST-C170TBKT_Blue 67.332,80.688 r90 bottom value=Blue
D6 "LTST-C170TBKT" LTST-C170TBKT_Blue 69.414,80.677 r90 bottom value=Blue
D7 "150080VS75000" WL-SMCW_Green_0805 128.51,46.525 r180 bottom value="Bright Green"
D8 "150080SS75000" WL-SMCW_RED_0805 133.473,81.033 r270 top value=Red
D9 "150080VS75000" WL-SMCW_Green_0805 136.638,81.018 r270 top value="Bright Green"
EC1 "controlCARD-120HSEC_Edge" controlCARD-120HSEC_Edge 75.557,26.436 r0 top locked
EC2 "controlCARD-180HSEC-60pinAddon_Edge" controlCARD-180HSEC-60pinAddon_Edge 134.955,26.436 r0 top locked
FID1 "Fiducial" Fiducial10-20#1 45.593,40.742 r0 top
FID2 "Fiducial" Fiducial10-20#1 45.593,40.742 r180 bottom
FID3 "Fiducial" Fiducial10-20#2 144.856,34.341 r0 top
FID4 "Fiducial" Fiducial10-20#2 144.856,34.341 r180 bottom
FID5 "Fiducial" Fiducial10-20#1 128.803,83.16 r0 top
FID6 "Fiducial" Fiducial10-20#1 128.803,83.16 r0 bottom
J1 "632723300011" Wurth_632_723_300_011 43.612,78.435 r270 top
J2 "2908-05WB-MG" 3M_2908-05WB-MG 115.757,79.893 r180 bottom
J3 "TMM-105-01-T-D" FP-TMM-105-01-T-D_HDR10-MFG 97.18,41.351 r0 top
J4 "632723300011" Wurth_632_723_300_011 88.925,85.446 r180 top
J5 "7498010210A" Wurth_7498010210A 145.234,70.248 r0 top
J6 "7498010210A" Wurth_7498010210A 145.234,48.362 r0 top
L1 "XFL4015-471MEC" XFL4015 136.653,42.308 r270 bottom value=470nH
L2 "XFL4015-471MEC" XFL4015 136.653,51.656 r90 bottom value=470nH
L3 "60 ohm" 0805_HV 102.308,54.246 r180 bottom
L4 "60 ohm" 0805_HV 83.922,42.748 r90 bottom
L5 "220 ohm" 0805_HV 107.693,57.244 r180 bottom
Logo1 "CE Mark" CE_Mark_5mm 139.608,35.16 r180 bottom
Logo2 "Texas Instruments" TI_Stacked_Overlay_Small 135.966,81.051 r180 bottom
Logo3 "FCC disclaimer" FCC_disclaimer 59.461,54.559 r0 top
Logo4 "WEEE logo" WEEE_Minimum 132.766,36.576 r180 bottom
Logo5 "ETHERCAT LABEL" EtherCAT_label 152.399,26.137 r90 top
R1 "AC0402FR-0710KL" 0402 75.034,63.311 r270 bottom value=10.0k
R2 "ERJ-2GE0R00X" 0402 129.56,43.426 r180 bottom value=0
R3 "CRCW04021K00JNED" 0402 55.698,62.78 r90 top value=1.0k
R4 "CRCW04021K00JNED" 0402 56.944,62.781 r90 top value=1.0k
R5 "CRCW04021K00JNED" 0402 58.163,62.781 r90 top value=1.0k
R6 "CRCW04021K00JNED" 0402 59.382,62.781 r90 top value=1.0k
R7 "CRCW0402100RJNED" 0402 59.03,70.782 r90 top value=100
R8 "ERJ-2RKF4700X" 0402 67.973,76.43 r270 bottom value=470
R9 "ERJ-2RKF4700X" 0402 69.24,76.429 r270 bottom value=470
R10 "AC0402FR-0710KL" 0402 51.737,64.356 r90 bottom value=10.0k
R11 "AC0402FR-0710KL" 0402 51.741,61.712 r90 bottom value=10.0k
R12 "CRCW04024K87FKED" 0402 57.254,58.33 r270 top value=4.87k
R13 "51" FP-RT0402FRE0751RL_0402-MFG 50.343,64.364 r90 bottom
R14 "CRCW0402680RJNED" 0402 51.686,70.579 r270 top value=680
R15 "RMCF0402FT1M00" 0402 49.024,78.996 r0 bottom value=1.00Meg
R16 "RC0603JR-075K1L" 0603 59.715,76.225 r90 bottom value=5.1k
R17 "RC0603JR-075K1L" 0603 61.29,76.225 r270 bottom value=5.1k
R18 "ERJ-3GEY0R00V" 0603 63.121,81.164 r270 bottom value=0
R19 "CRCW06032K20JNEA" 0603 75.768,73.914 r180 top value=2.2k
R20 "ERJ-3GEY0R00V" 0603 75.768,69.773 r180 top value=0
R21 "RC0603FR-071KL" 0603 81.178,68.937 r180 top value=1.00k
R22 "CRCW060310K0JNEA" 0603 75.782,70.382 r0 bottom value=10k
R23 "CRCW060310K0JNEA" 0603 79.169,75.532 r0 bottom value=10k
R24 "RC0603JR-074K7L" 0603 82.246,80.033 r180 bottom value=4.7k
R25 "RC0603FR-07430RL" 0603 81.204,70.51 r180 top value=430
R26 "RC0603JR-071K2L" 0603 82.246,78.458 r0 bottom value=1.2k
R27 "ERJ-3GEY0R00V" 0603 82.042,72.949 r90 top value=0
R28 "ERJ-3GEY0R00V" 0603 82.271,82.245 r180 bottom value=0
R29 "ERJ-3GEY0R00V" 0603 82.271,83.871 r180 bottom value=0
R30 "CRCW040288K7FKED" 0402 142.113,43.144 r180 bottom value=88.7k
R31 "AC0402FR-0710KL" 0402 94.437,73.584 r90 bottom value=10.0k
R32 "CRG0402F4K7" 0402 117.648,67.322 r0 top value=4.70k
R33 "ERJ-3GEY0R00V" 0603 96.998,67.625 r270 top value=0
R34 "CRCW0402680RJNED" 0402 102.435,62.476 r270 bottom value=680
R35 "CRCW0402680RJNED" 0402 112.595,62.527 r270 bottom value=680
R36 "AC0402FR-0710KL" 0402 110.452,82.923 r90 top value=10.0k
R37 "AC0402FR-0710KL" 0402 111.908,82.963 r90 top value=10.0k
R38 "AC0402FR-0710KL" 0402 106.575,44.381 r0 top value=10.0k
R39 "CRCW04021M50JNED" 0402 102.956,61.83 r180 top value=1.5Meg
R40 "CRCW04021M50JNED" 0402 107.043,57.353 r0 top value=1.5Meg
R41 "RG1005P-104-B-T5" 0402 116.459,54.972 r90 top value=100k
R42 "CRCW04023K30JNED" 0402 104.089,36.144 r270 bottom value=3.3k
R43 "AC0402FR-0710KL" 0402 107.54,82.923 r270 top value=10.0k
R44 "ERJ-3GEY0R00V" 0603 102.006,72.06 r90 top value=0
R45 "ERJ-3GEY0R00V" 0603 94.683,37.142 r270 top value=0
R46 "ERJ-2GE0R00X" 0402 102.387,52.4 r90 top value=0
R47 "ERJ-3GEY0R00V" 0603 96.316,37.142 r270 top value=0
R48 "CRCW04020000Z0EDHP" 0402 101.134,52.386 r90 top value=0
R49 "ERJ-3GEY0R00V" 0603 106.604,80.112 r180 top value=0
R50 "ERJ-3GEY0R00V" 0603 97.949,37.142 r270 top value=0
R51 "AC0402FR-0710KL" 0402 101.19,67.937 r90 top value=10.0k
R52 "ERJ-3GEY0R00V" 0603 98.577,67.64 r90 top value=0
R53 "CRCW0603100KJNEA" 0603 145.655,47.539 r0 bottom value=100k
R54 "AC0402FR-0710KL" 0402 99.997,67.937 r90 top value=10.0k
R55 "ERJ-3GEY0R00V" 0603 107.402,77.653 r90 top value=0
R56 "ERJ-3GEY0R00V" 0603 101.215,37.142 r270 top value=0
R57 "RC0603FR-071KL" 0603 81.064,44.028 r180 top value=1.00k
R58 "ERJ-2GE0R00X" 0402 106.909,68.548 r180 top value=0
R59 "ERJ-3GEY0R00V" 0603 117.142,61.321 r270 bottom value=0
R60 "ERJ-3GEY0R00V" 0603 118.706,62.476 r90 bottom value=0
R61 "CRCW04023K30JNED" 0402 104.877,78.207 r90 bottom value=3.3k
R62 "CRCW040256K0JNED" 0402 140.106,58.369 r90 bottom value=56k
R63 "CRCW040256K0JNED" 0402 130.885,58.369 r90 bottom value=56k
R64 "ERJ-3GEY0R00V" 0603 120.255,61.321 r270 bottom value=0
R65 "CPF0402B10RE1" CPF0402 129.145,68.906 r90 bottom value=10.0
R66 "ERJ-3GEY0R00V" 0603 121.869,62.471 r90 bottom value=0
R67 "CPF0402B10RE1" CPF0402 136.231,64.178 r270 bottom value=10.0
R68 "CPF0402B10RE1" CPF0402 132.904,68.906 r90 bottom value=10.0
R69 "CRCW04020000Z0EDHP" 0402 141.601,64.355 r270 bottom value=0
R70 "ERJ-3GEY0R00V" 0603 114.027,61.321 r90 bottom value=0
R71 "CRCW04020000Z0EDHP" 0402 84.912,71.298 r90 bottom value=0
R72 "AC0402FR-0710KL" 0402 86.182,71.298 r90 bottom value=10.0k
R73 "ERJ-2GE0R00X" 0402 130.415,69.149 r270 bottom value=0
R74 "CRCW04020000Z0EDHP" 0402 131.648,69.164 r90 bottom value=0
R75 "ERJ-3GEY0R00V" 0603 115.53,62.476 r90 bottom value=0
R76 "CRCW04020000Z0EDHP" 0402 141.931,71.457 r270 bottom value=0
R77 "RMCF0402FT1M00" 0402 87.269,79.189 r0 bottom value=1.00Meg
R78 "ERJ-3GEY0R00V" 0603 105.791,77.648 r90 top value=0
R79 "RC0603JR-075K1L" 0603 91.156,74.621 r180 bottom value=5.1k
R80 "ERJ-2GE0R00X" 0402 96.774,72.365 r0 bottom value=0
R81 "ERJ-2GE0R00X" 0402 96.799,71.099 r0 bottom value=0
R82 "ERJ-2GE0R00X" 0402 102.18,55.88 r180 top value=0
R83 "ERJ-2GE0R00X" 0402 111.283,65.854 r270 top value=0
R84 "ERJ-2GE0R00X" 0402 110.054,65.854 r270 top value=0
R85 "ERJ-6GEYJ103V" 0805_HV 96.998,67.764 r0 bottom value=10k
R86 "ERJ-2GE0R00X" 0402 108.825,65.854 r270 top value=0
R87 "ERJ-2GE0R00X" 0402 106.909,67.327 r180 top value=0
R88 "CRCW04022K49FKED" 0402 103.734,69.52 r180 bottom value=2.49k
R89 "CRCW04022K49FKED" 0402 118.542,82.067 r0 top value=2.49k
R90 "CRCW0603100KJNEA" 0603 91.742,69.602 r180 bottom value=100k
R91 "ERJ-2GE0R00X" 0402 106.575,46.864 r180 top value=0
R92 "ERJ-2GE0R00X" 0402 111.165,44.366 r270 top value=0
R93 "ERJ-2GE0R00X" 0402 94.463,79.911 r90 bottom value=0
R94 "CRCW0402680RJNED" 0402 129.56,44.721 r0 bottom value=680
R95 "CRCW040219K6FKED" 0402 142.138,41.885 r0 bottom value=19.6k
R96 "ERJ-3GEY0R00V" 0603 93.051,37.142 r90 top value=0
R97 "ERJ-2GE0R00X" 0402 142.108,45.687 r0 bottom value=0
R98 "ERJ-3GEY0R00V" 0603 99.583,37.142 r90 top value=0
R99 "ERJ-2GE0R00X" 0402 132.6,46.463 r180 bottom value=0
R100 "AC0402FR-0710KL" 0402 78.105,62.586 r270 top value=10.0k
R101 "ERJ-2GE0R00X" 0402 129.56,52.011 r180 bottom value=0
R102 "CRCW040268K0JNED" 0402 142.125,52.016 r0 bottom value=68k
R103 "AC0402FR-0710KL" 0402 142.113,44.425 r0 bottom value=10.0k
R104 "CRCW0603100KJNEA" 0603 145.669,45.923 r180 bottom value=100k
R105 "CRG0402F4K7" 0402 96.85,64.76 r0 bottom value=4.70k
R106 "CRG0402F4K7" 0402 96.825,66.005 r0 bottom value=4.70k
R107 "CRCW04022K20FKED" 0402 118.988,76.842 r90 top value=2.20k
R108 "CRG0402F4K7" 0402 106.909,70.989 r0 top value=4.70k
R109 "CRCW04026K49FKED" 0402 120.193,76.842 r270 top value=6.49k
R110 "ERJ-2GE0R00X" 0402 109.913,44.366 r270 top value=0
R111 "CRCW04022K49FKED" 0402 115.875,82.067 r180 top value=2.49k
R112 "CRCW04022K49FKED" 0402 104.45,71.845 r270 bottom value=2.49k
R113 "CRCW04022K49FKED" 0402 122.718,78.938 r180 bottom value=2.49k
R114 "CRCW040233R2FKED" 0402 106.909,73.43 r0 top value=33.2
R115 "CRCW040233R2FKED" 0402 106.909,74.651 r0 top value=33.2
R116 "CRCW040233R2FKED" 0402 115.374,76.842 r270 top value=33.2
R117 "CRCW040233R2FKED" 0402 116.578,76.842 r270 top value=33.2
R118 "CRCW040233R2FKED" 0402 117.783,76.842 r270 top value=33.2
R119 "CRCW040233R2FKED" 0402 106.909,72.21 r0 top value=33.2
R120 "CRCW040233R2FKED" 0402 106.909,69.768 r0 top value=33.2
R121 "CRCW040233R2FKED" 0402 112.512,65.854 r90 top value=33.2
R122 "CRCW040233R2FKED" 0402 113.741,65.854 r90 top value=33.2
R123 "CRCW04022K20FKED" 0402 115.697,63.602 r180 top value=2.20k
R124 "CRCW04022K20FKED" 0402 115.672,64.821 r180 top value=2.20k
R125 "CRCW04022K20FKED" 0402 115.672,66.04 r180 top value=2.20k
R126 "CRCW040233R2FKED" 0402 114.169,76.842 r270 top value=33.2
R127 "CRCW04022K49FKED" 0402 106.604,65.522 r270 bottom value=2.49k
R128 "CRCW04022K49FKED" 0402 122.715,77.714 r180 bottom value=2.49k
R129 "CRCW04022K49FKED" 0402 128.676,75.438 r90 bottom value=2.49k
R130 "CRCW04022K49FKED" 0402 106.562,50.504 r0 bottom value=2.49k
R131 "RMCF0402ZT0R00" "FP-RMCF0402ZT0R00_0402 (1005 metric)-0" 119.249,67.495 r90 bottom
R132 "CRCW0603470RJNEA" 0603 120.102,66.337 r270 top value=470
R133 "CRCW04022K49FKED" 0402 113.428,55.572 r0 bottom value=2.49k
R134 "RMCF0402ZT0R00" "FP-RMCF0402ZT0R00_0402 (1005 metric)-0" 113.178,76.766 r90 top
R135 "CRCW0603470RJNEA" 0603 122.463,79.294 r270 top value=470
R136 "RMCF0402FT1M00" 0402 141.032,80.993 r270 top value=1.00Meg
R137 "CRCW04021K27FKED" 0402 125.665,59.885 r180 top value=1.27k
R138 "CRCW0402680RJNED" 0402 125.651,58.615 r0 top value=680
R139 "CRCW04021M50JNED" 0402 138.111,58.437 r0 top value=1.5Meg
R140 "CRCW04021M50JNED" 0402 138.06,59.86 r0 top value=1.5Meg
R141 "CRG0402F4K7" 0402 117.674,45.93 r0 top value=4.70k
R142 "CRG0402F4K7" 0402 106.578,49.352 r0 top value=4.70k
R143 "CRCW04026K49FKED" 0402 117.699,54.972 r270 top value=6.49k
R144 "ERJ-2GE0R00X" 0402 108.661,44.366 r270 top value=0
R145 "CRCW04022K49FKED" 0402 112.98,58.336 r90 bottom value=2.49k
R146 "CRCW04022K49FKED" 0402 104.044,47.624 r270 bottom value=2.49k
R147 "CRCW04022K49FKED" 0402 111.735,58.344 r270 bottom value=2.49k
R148 "CRCW040233R2FKED" 0402 106.575,51.83 r0 top value=33.2
R149 "CRCW040233R2FKED" 0402 106.575,53.072 r0 top value=33.2
R150 "CRCW040233R2FKED" 0402 111.497,54.972 r270 top value=33.2
R151 "CRCW04022K20FKED" 0402 115.606,44.188 r0 top value=2.20k
R152 "CRCW040233R2FKED" 0402 112.738,54.972 r270 top value=33.2
R153 "CRCW040233R2FKED" 0402 113.978,54.972 r270 top value=33.2
R154 "CRCW040233R2FKED" 0402 106.575,50.589 r0 top value=33.2
R155 "CRCW040233R2FKED" 0402 106.575,48.105 r0 top value=33.2
R156 "CRCW040233R2FKED" 0402 112.417,44.366 r90 top value=33.2
R157 "CRCW040233R2FKED" 0402 113.669,44.366 r90 top value=33.2
R158 "CRCW040233R2FKED" 0402 110.257,54.972 r270 top value=33.2
R159 "CRCW04022K20FKED" 0402 115.657,41.724 r180 top value=2.20k
R160 "CRCW04022K20FKED" 0402 115.632,42.969 r180 top value=2.20k
R161 "CRCW04022K49FKED" 0402 104.898,52.494 r90 bottom value=2.49k
R162 "CRCW04022K49FKED" 0402 110.49,58.344 r270 bottom value=2.49k
R163 "CRCW04022K49FKED" 0402 117.674,45.38 r0 bottom value=2.49k
R166 "RMCF0402ZT0R00" "FP-RMCF0402ZT0R00_0402 (1005 metric)-0" 119.96,47.683 r90 bottom
R167 "CRCW0603470RJNEA" 0603 120.102,44.848 r270 top value=470
R168 "RMCF0402ZT0R00" "FP-RMCF0402ZT0R00_0402 (1005 metric)-0" 106.172,52.257 r90 bottom
R169 "CRCW0603470RJNEA" 0603 121.992,56.319 r180 top value=470
R170 "RMCF0402FT1M00" 0402 141.032,38.481 r90 top value=1.00Meg
R171 "CRCW040215K0FKED" 0402 142.108,48.354 r180 bottom value=15.0k
R172 "ERJ-3GEY0R00V" 0603 49.48,42.277 r270 top value=0
R173 "ERJ-3GEY0R00V" 0603 51.057,42.277 r270 top value=0
R174 "ERJ-3GEY0R00V" 0603 52.63,42.277 r270 top value=0
R175 "ERJ-3GEY0R00V" 0603 54.211,42.277 r270 top value=0
R176 "ERJ-3GEY0R00V" 0603 55.789,42.277 r270 top value=0
R177 "ERJ-3GEY0R00V" 0603 57.366,42.277 r270 top value=0
R178 "ERJ-3GEY0R00V" 0603 62.072,42.261 r270 bottom value=0
R179 "ERJ-3GEY0R00V" 0603 63.649,42.261 r270 bottom value=0
R180 "ERJ-3GEY0R00V" 0603 65.226,42.261 r270 bottom value=0
R181 "ERJ-3GEY0R00V" 0603 66.828,42.277 r270 bottom value=0
R182 "ERJ-3GEY0R00V" 0603 58.943,42.277 r270 top value=0
R183 "ERJ-3GEY0R00V" 0603 60.52,42.277 r270 top value=0
R184 "ERJ-3GEY0R00V" 0603 49.48,42.277 r270 bottom value=0
R185 "ERJ-3GEY0R00V" 0603 51.057,42.277 r270 bottom value=0
R186 "ERJ-3GEY0R00V" 0603 52.609,42.261 r270 bottom value=0
R187 "ERJ-3GEY0R00V" 0603 54.186,42.261 r270 bottom value=0
R188 "ERJ-3GEY0R00V" 0603 55.764,42.261 r270 bottom value=0
R189 "ERJ-3GEY0R00V" 0603 57.341,42.261 r270 bottom value=0
R190 "ERJ-3GEY0R00V" 0603 62.097,42.277 r270 top value=0
R191 "ERJ-3GEY0R00V" 0603 63.674,42.277 r270 top value=0
R192 "ERJ-3GEY0R00V" 0603 60.495,42.261 r270 bottom value=0
R193 "ERJ-3GEY0R00V" 0603 58.918,42.261 r270 bottom value=0
R194 "ERJ-3GEY0R00V" 0603 65.251,42.277 r270 top value=0
R195 "ERJ-3GEY0R00V" 0603 66.828,42.277 r270 top value=0
R196 "ERJ-3GEY0R00V" 0603 84.781,38.208 r90 bottom value=0
R197 "ERJ-3GEY0R00V" 0603 88.515,38.208 r90 bottom value=0
R198 "ERJ-3GEY0R00V" 0603 86.648,38.208 r90 bottom value=0
R199 "ERJ2BWFR100X" 0402 76.81,48.514 r0 top value=0.1
R200 "ERJ2BWFR100X" 0402 87.274,42.088 r90 bottom value=0.1
R201 "ERJ2BWFR100X" 0402 76.839,53.308 r0 top value=0.1
R202 "CRCW04022K20FKED" 0402 95.882,43.807 r0 bottom value=2.20k
R203 "ERJ-2GE0R00X" 0402 106.575,45.622 r180 top value=0
R204 "CRG0402F4K7" 0402 47.803,42.17 r90 top value=4.70k
R205 "CRG0402F4K7" 0402 47.794,42.188 r270 bottom value=4.70k
R206 "CRCW040268K0JNED" 0402 142.108,50.759 r180 bottom value=68k
R212 "ERJ-3GEY0R00V" 0603 103.658,72.067 r90 top value=0
S1 "218-2LPST" SW_218-2LP 82.61,65.92 r0 top
S2 "CAS-D20TA" SW_CAS-D20TA 98.273,72.085 r270 top
S3 "CAS-D20TA" SW_CAS-D20TA 135.495,58.133 r180 bottom
S4 "1188E-1K2-V-TR" SW_1188E 100.66,82.423 r270 top
S5 "CAS-D20TA" SW_CAS-D20TA 88.984,36.685 r90 top
S6 "CAS-D20TA" SW_CAS-D20TA 82.689,36.685 r90 top
T1 "750315371" Wurth_750315371 69.974,79.062 r180 top value=105uH
TP1 "TESTPOINT" TP_50MIL-25MILHOLE 46.885,67.023 r0 top
TP2 "TESTPOINT" TP_50MIL-25MILHOLE 46.885,60.52 r0 top
TP3 "TESTPOINT" TP_50MIL-25MILHOLE 51.279,57.802 r0 top
TP4 "TESTPOINT" TP_50MIL-25MILHOLE 45.745,43.917 r90 top
TP5 "TESTPOINT" TP_50MIL-25MILHOLE 45.745,49.251 r90 top
TP6 "TESTPOINT" TP_50MIL-25MILHOLE 101.676,45.974 r90 top
TP7 "TESTPOINT" TP_50MIL-25MILHOLE 101.697,58.757 r90 top
TP8 "TESTPOINT" TP_50MIL-25MILHOLE 45.745,46.584 r90 top
TP9 "TESTPOINT" TP_50MIL-25MILHOLE 95.043,83.268 r0 top
TP10 "TESTPOINT" TP_50MIL-25MILHOLE 99.716,56.877 r90 top
TP11 "TESTPOINT" TP_50MIL-25MILHOLE 107.594,42.062 r0 top
U1 "TMS320F28P650DK9ZEJ" ZEJ0256A-MFG 88.641,53.195 r0 top
U2 "MSP432E401YTPDT" PDT0128A 61.235,65.666 r180 bottom
U3 "SN6505BDBVR" DBV0006A_L 60.2,81.18 r180 top
U4 "TPD4E05U06DQAR" DQA0010A#1 58.594,77.172 r90 top
U5 "TPS2113ADRBR" DRB0008B 79.299,72.868 r180 bottom
U6 "ISO7762DBQR" DBQ0016A_N 72.182,65.025 r0 top
U7 "SN74CB3Q3244PWR" PW0020A-MFG 80.442,66.421 r0 bottom
U8 "TLV70333DBVR" DBV0005A-MFG 50.213,64.025 r0 top
U9 "TPD6E05U06RVZR" RVZ0014A 55.369,36.695 r90 top
U10 "SN74LVC2G07DBVR" DBV0006A_N 105,59.428 r0 top
U11 "TPS3703A4330DSERQ1" DSE0006A 97.708,76.029 r0 top
U12 "TPS3850G12QDRCRQ1" DRC0010R 101.408,77.589 r0 top
U13 "TPD4E05U06DQAR" DQA0010A#2 88.46,71.668 r90 bottom
U14 "TPS2051BDBVR" DBV0005A_N 92.05,67.158 r180 bottom
U15 "TPS62442WRQRR" RQR0014A-MFG 137.273,47.007 r180 bottom
U16 "CAT24C16WI-GT3" SOIC-8 90.957,66.751 r0 top
U17 "TPD4E05U06DQAR" DQA0010A#1 118.143,71.887 r0 top
U18 "SN74LVC2G06DBVR" DBV0006A_N 133.412,59.25 r180 top
U19 "TPD4E05U06DQAR" DQA0010A#1 118.059,50.618 r0 top
U20 "TPD6E05U06RVZR" RVZ0014A 63.522,36.695 r90 top
U21 "TPD6E05U06RVZR" RVZ0014A 63.549,36.668 r270 bottom
U22 "TPD6E05U06RVZR" RVZ0014A 55.396,36.668 r270 bottom
U23 "REF5030AIDR" D0008A_N 75.844,39.091 r0 top
U24 "OPA4350EA/250" DBQ0016A_N 75.789,45.016 r0 top
U25 "DP83826IRHBR" RHB0032M-MFG 112.685,71.137 r180 top
U26 "DP83826IRHBR" RHB0032M-MFG 112.685,49.649 r180 top
Y1 "830064296" FP-830064296_SMT4_3MM4_2MM7-MFG 47.625,71.044 r90 bottom
Y2 "LMK6CE02500CDLFT" DLF0004A-MFG 138.852,64.229 r180 bottom
Y3 "LMK6CE02000CDLFT" DLF0004A-MFG 138.852,71.391 r180 bottom
ZZ1 "This Assembly Note is for PCB labels only" AssemblyNoteLabel -26.187,112.141 r0 top
ZZ2 "These assemblies are ESD sensitive, ESD precautions shall be observed." AssemblyNote -26.213,109.55 r0 top
ZZ3 "These assemblies must be clean and free from flux and all contaminants. Use of no clean flux is not acceptable." AssemblyNote -26.314,106.858 r0 top
ZZ4 "These assemblies must comply with workmanship standards IPC-A-610 Class 2, unless otherwise specified." AssemblyNote -26.441,104.369 r0 top

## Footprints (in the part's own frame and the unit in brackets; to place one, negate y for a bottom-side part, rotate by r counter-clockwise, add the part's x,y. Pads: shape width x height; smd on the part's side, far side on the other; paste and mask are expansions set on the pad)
3M_2908-05WB-MG [mm] "Connector, Micro SD, R/A, SMD"
  rect 0.8x1.5 smd: 1(0,0) 2(1.1,-0.4) 3(2.2,0) 4(3.3,0.2) 5(4.4,0) 6(5.5,0.2) 7(6.6,0) 8(7.7,0)
  rect 1.4x1.9 smd: S1(-4.66,3.85) S2(8.49,2.85)
  rect 1.8x1.4 smd: S3(6.89,-10.3) S4(1.19,-10.3)
  silkscreen extent -5.06,-10.7 8.94,4.45, body extent -5.06,-10.75 8.94,4.5, height 1.91
0402 [mm] "0402 from SM-752 data"
  rect 0.8x0.6 smd: 1(-0.6,0) 2(0.6,0)
  silkscreen extent -1.22,-0.52 1.22,0.52, body extent -0.55,-0.3 0.55,0.3, height 0.6
0402_065 [mm] "0402"
  rect 0.8x0.6 smd: 1(-0.6,0) 2(0.6,0)
  silkscreen extent -1.22,-0.52 1.22,0.52, body extent -0.55,-0.3 0.55,0.3, height 0.65
0603 [mm] "0603 from SM-752 data"
  rect 1x0.95 smd: 1(-0.8,0) 2(0.8,0)
  silkscreen extent -1.52,-0.69 1.52,0.69, body extent -0.87,-0.47 0.87,0.47, height 1
0805_HV [mil] "0805 with 30mil clearance between pads"
  rect 50x63 smd: 1(-40,0) 2(40,0)
  silkscreen extent -74,-40 74,40, body extent -43,-29 43,29, height 57
1812_180 [mm] "SMT, 2-Leads, Body 4.5x3.2mm"
  rect 1.473x4.36 smd: 1(-2.784,0) 2(2.784,0)
  silkscreen extent -3.75,-2.48 3.75,2.48, body extent -2.43,-1.75 2.42,1.75, height 1.8
3216-18 [mm] "Based on AVX recommendation in http://www.avx.com/download/software/literature/AVX-Footprint-Library.pdf"
  rrect7% 1.4x1.8 smd: 1(-1.3,0) 2(1.3,0)
  silkscreen extent -1.9,-1.12 0.8,1.12, body extent -1.7,-0.9 1.7,0.9, height 1.82
AssemblyNote [mm] "Assembly Note"
AssemblyNoteLabel [mm] "Assembly Note for PCB Labels"
CE_Mark_5mm [mm] "Minimum text height for CE Mark"
  silkscreen extent -3.5,-2.5 3.5,2.5
controlCARD-120HSEC_Edge [mm] "Edge Connector, 0.8mm, 60x2, pad numbers do not match Samtec datasheet"
  rect 0.55x2.8 smd paste-2.5 mask+0: 1(-23.6,2.4) 3(-22.8,2.4) 5(-22,2.4) 7(-21.2,2.4) 9(-20.4,2.4) 11(-19.6,2.4) 13(-18.8,2.4) 15(-18,2.4) 17(-17.2,2.4) 19(-16.4,2.4) 21(-15.6,2.4) 23(-14.8,2.4) 25(-14,2.4) 27(-13.2,2.4) 29(-12.4,2.4) 31(-11.6,2.4) 33(-10.8,2.4) 35(-10,2.4) 37(-9.2,2.4) 39(-8.4,2.4) 41(-7.6,2.4) 43(-6.8,2.4) 45(-6,2.4) 47(-5.2,2.4) 49(-4.4,2.4) 51(-3.6,2.4) 53(-2.8,2.4) 55(-2,2.4) 57(2,2.4) 59(2.8,2.4) 61(3.6,2.4) 63(4.4,2.4) 65(5.2,2.4) 67(6,2.4) 69(6.8,2.4) 71(7.6,2.4) 73(8.4,2.4) 75(9.2,2.4) 77(10,2.4) 79(10.8,2.4) 81(11.6,2.4) 83(12.4,2.4) 85(13.2,2.4) 87(14,2.4) 89(14.8,2.4) 91(15.6,2.4) 93(16.4,2.4) 95(17.2,2.4) 97(18,2.4) 99(18.8,2.4) 101(19.6,2.4) 103(20.4,2.4) 105(21.2,2.4) 107(22,2.4) 109(22.8,2.4) 111(23.6,2.4) 113(24.4,2.4) 115(25.2,2.4) 117(26,2.4) 119(26.8,2.4)
  rect 0.55x2.8 smd far side paste-2.5 mask+0: 2(-23.6,2.4) 4(-22.8,2.4) 6(-22,2.4) 8(-21.2,2.4) 10(-20.4,2.4) 12(-19.6,2.4) 14(-18.8,2.4) 16(-18,2.4) 18(-17.2,2.4) 20(-16.4,2.4) 22(-15.6,2.4) 24(-14.8,2.4) 26(-14,2.4) 28(-13.2,2.4) 30(-12.4,2.4) 32(-11.6,2.4) 34(-10.8,2.4) 36(-10,2.4) 38(-9.2,2.4) 40(-8.4,2.4) 42(-7.6,2.4) 44(-6.8,2.4) 46(-6,2.4) 48(-5.2,2.4) 50(-4.4,2.4) 52(-3.6,2.4) 54(-2.8,2.4) 56(-2,2.4) 58(2,2.4) 60(2.8,2.4) 62(3.6,2.4) 64(4.4,2.4) 66(5.2,2.4) 68(6,2.4) 70(6.8,2.4) 72(7.6,2.4) 74(8.4,2.4) 76(9.2,2.4) 78(10,2.4) 80(10.8,2.4) 82(11.6,2.4) 84(12.4,2.4) 86(13.2,2.4) 88(14,2.4) 90(14.8,2.4) 92(15.6,2.4) 94(16.4,2.4) 96(17.2,2.4) 98(18,2.4) 100(18.8,2.4) 102(19.6,2.4) 104(20.4,2.4) 106(21.2,2.4) 108(22,2.4) 110(22.8,2.4) 112(23.6,2.4) 114(24.4,2.4) 116(25.2,2.4) 118(26,2.4) 120(26.8,2.4)
controlCARD-180HSEC-60pinAddon_Edge [mm] "Edge Connector, 0.8mm, 30x2, pad numbers do not match Samtec datasheet"
  rect 0.55x2.8 smd paste-2.5 mask+0: 121(-11.6,2.4) 123(-10.8,2.4) 125(-10,2.4) 127(-9.2,2.4) 129(-8.4,2.4) 131(-7.6,2.4) 133(-6.8,2.4) 135(-6,2.4) 137(-5.2,2.4) 139(-4.4,2.4) 141(-3.6,2.4) 143(-2.8,2.4) 145(-2,2.4) 147(-1.2,2.4) 149(-0.4,2.4) 151(0.4,2.4) 153(1.2,2.4) 155(2,2.4) 157(2.8,2.4) 159(3.6,2.4) 161(4.4,2.4) 163(5.2,2.4) 165(6,2.4) 167(6.8,2.4) 169(7.6,2.4) 171(8.4,2.4) 173(9.2,2.4) 175(10,2.4) 177(10.8,2.4) 179(11.6,2.4)
  rect 0.55x2.8 smd far side paste-2.5 mask+0: 122(-11.6,2.4) 124(-10.8,2.4) 126(-10,2.4) 128(-9.2,2.4) 130(-8.4,2.4) 132(-7.6,2.4) 134(-6.8,2.4) 136(-6,2.4) 138(-5.2,2.4) 140(-4.4,2.4) 142(-3.6,2.4) 144(-2.8,2.4) 146(-2,2.4) 148(-1.2,2.4) 150(-0.4,2.4) 152(0.4,2.4) 154(1.2,2.4) 156(2,2.4) 158(2.8,2.4) 160(3.6,2.4) 162(4.4,2.4) 164(5.2,2.4) 166(6,2.4) 168(6.8,2.4) 170(7.6,2.4) 172(8.4,2.4) 174(9.2,2.4) 176(10,2.4) 178(10.8,2.4) 180(11.6,2.4)
CPF0402 [mm] "TE Connectivity"
  rect 0.5x0.6 smd: 1(-0.5,0) 2(0.5,0)
  silkscreen extent -0.97,-0.53 0.97,0.53, body extent -0.55,-0.27 0.55,0.27, height 0.35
